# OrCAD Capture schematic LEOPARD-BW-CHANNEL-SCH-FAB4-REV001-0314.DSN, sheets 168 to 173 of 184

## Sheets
168 120_POWER/RESET BUTTON: size Custom; title: POWER/RESET BUTTON
169 036_CPU1 - GROUND (1/2): size A3; title: CPU1 - GROUND (1/2)
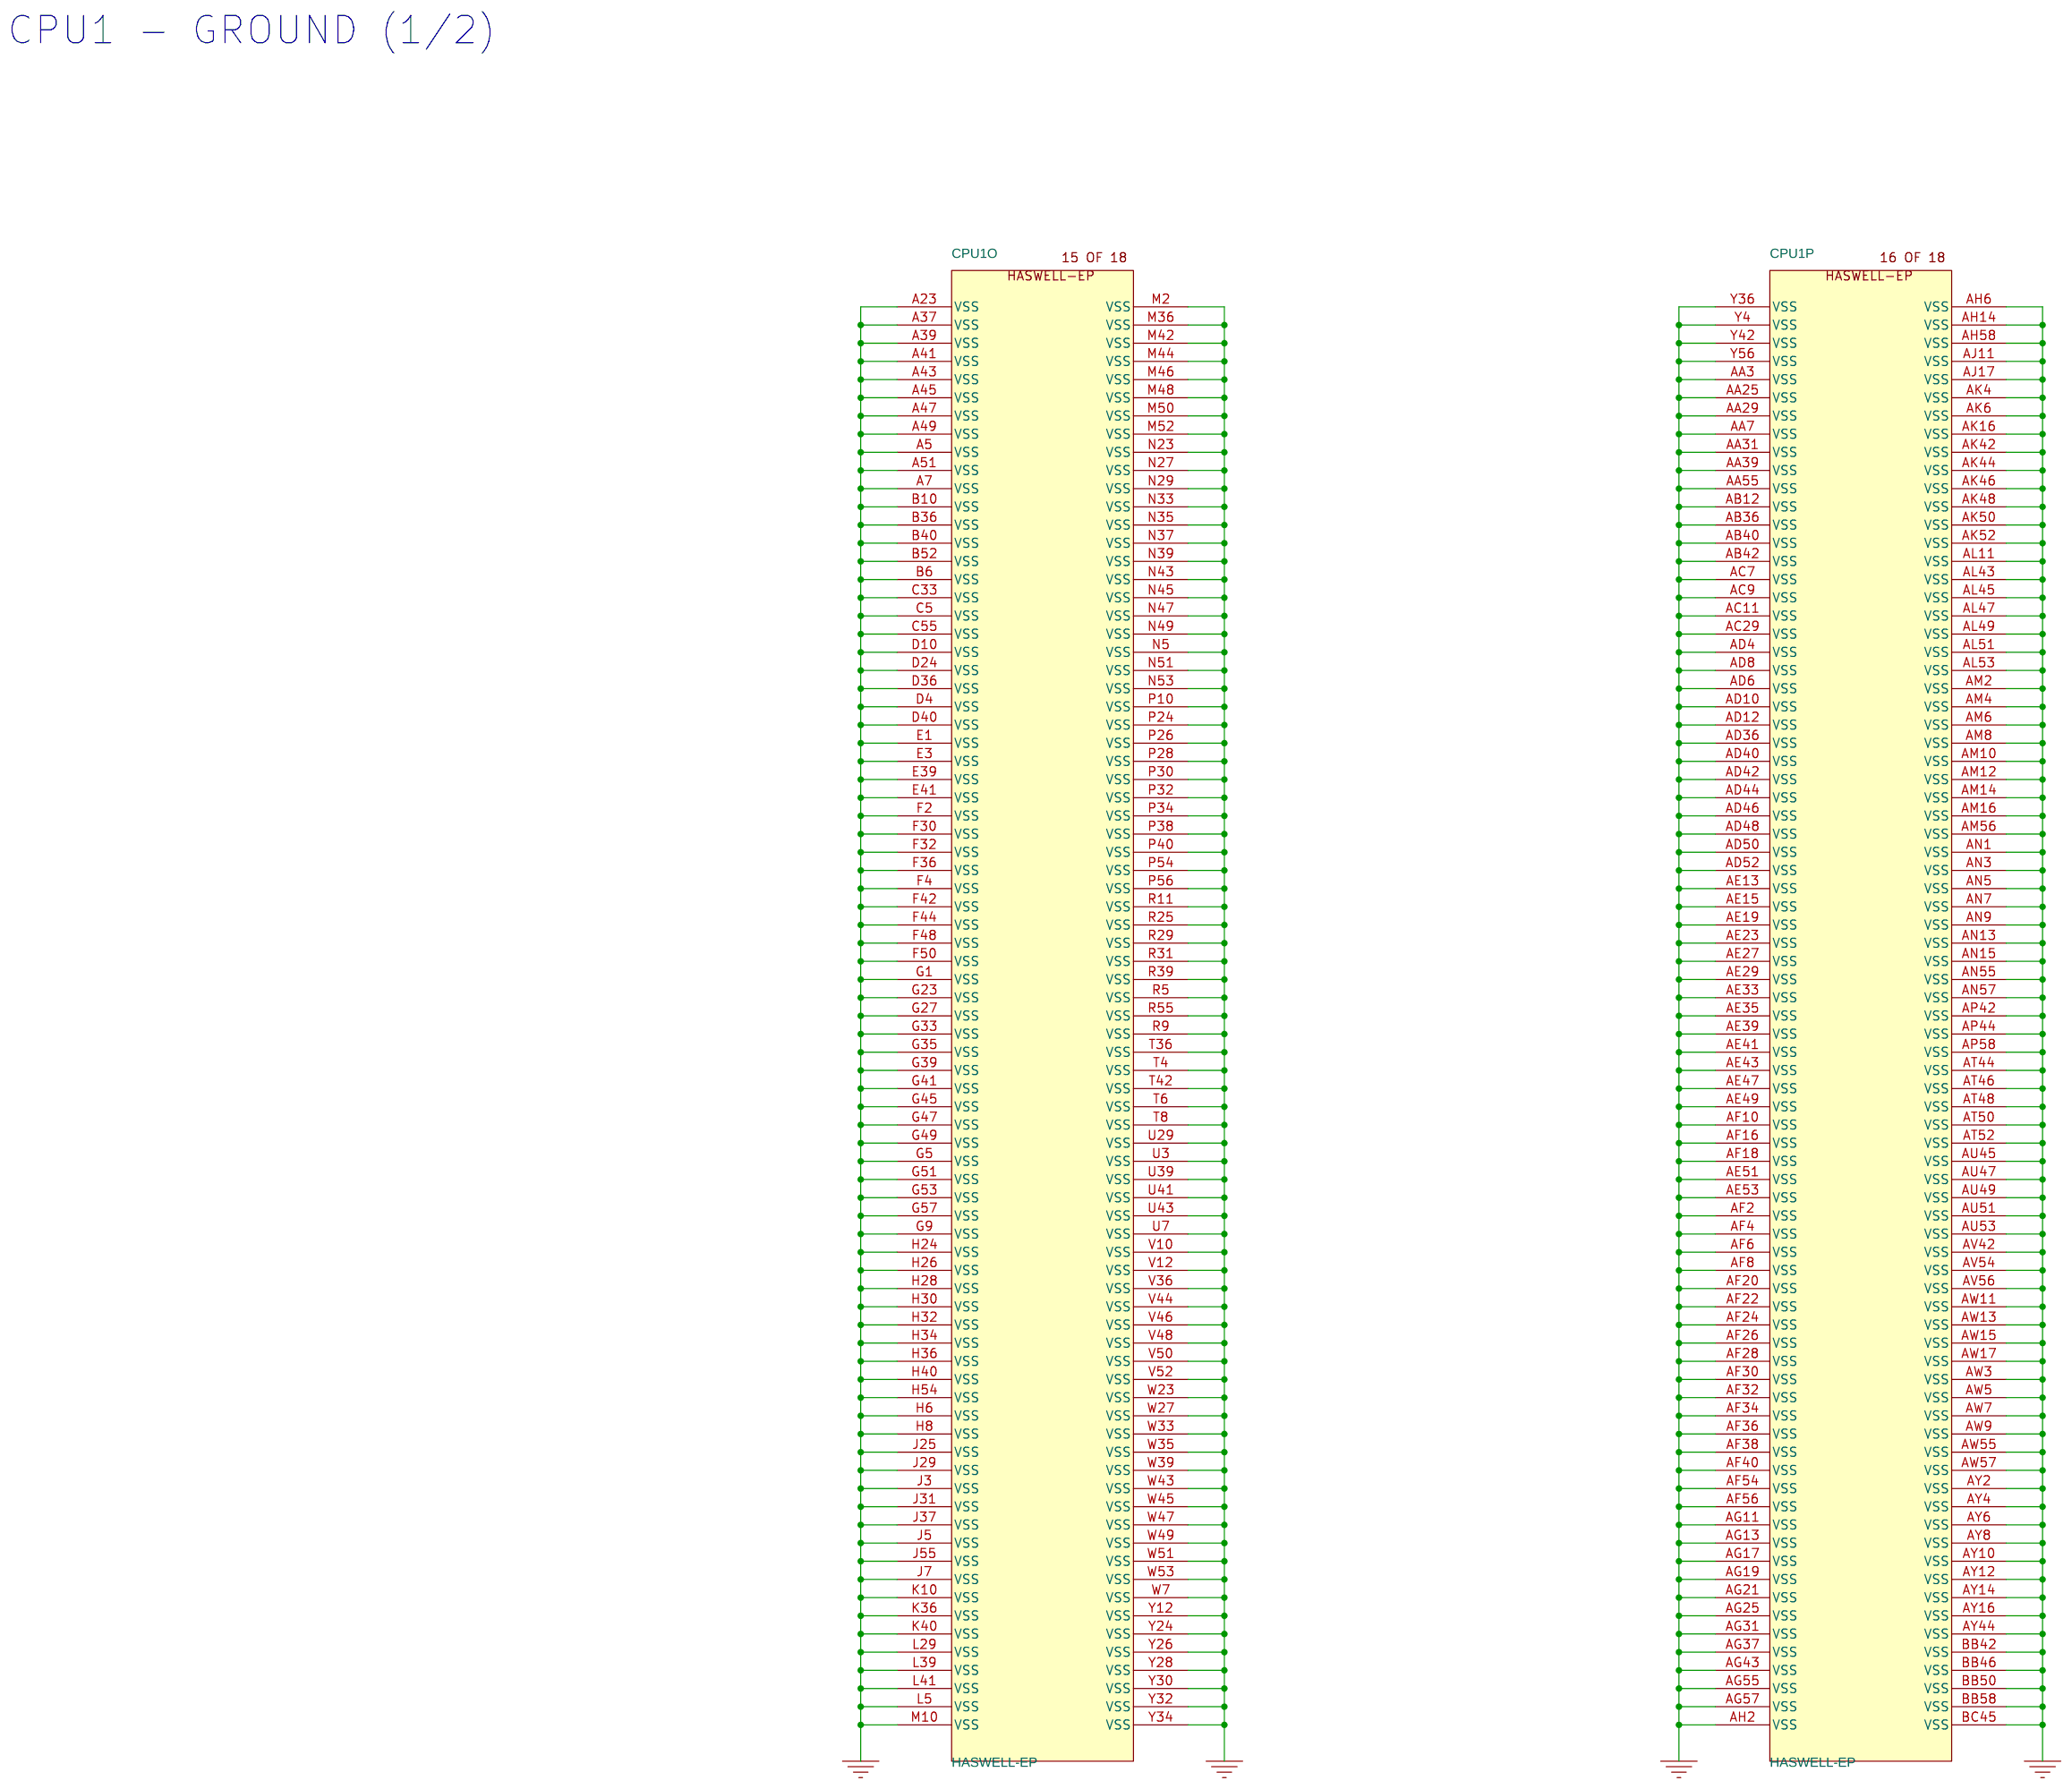
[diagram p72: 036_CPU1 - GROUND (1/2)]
170 037_CPU1 - GROUND (2/2): size A3; title: CPU1 - GROUND (2/2)
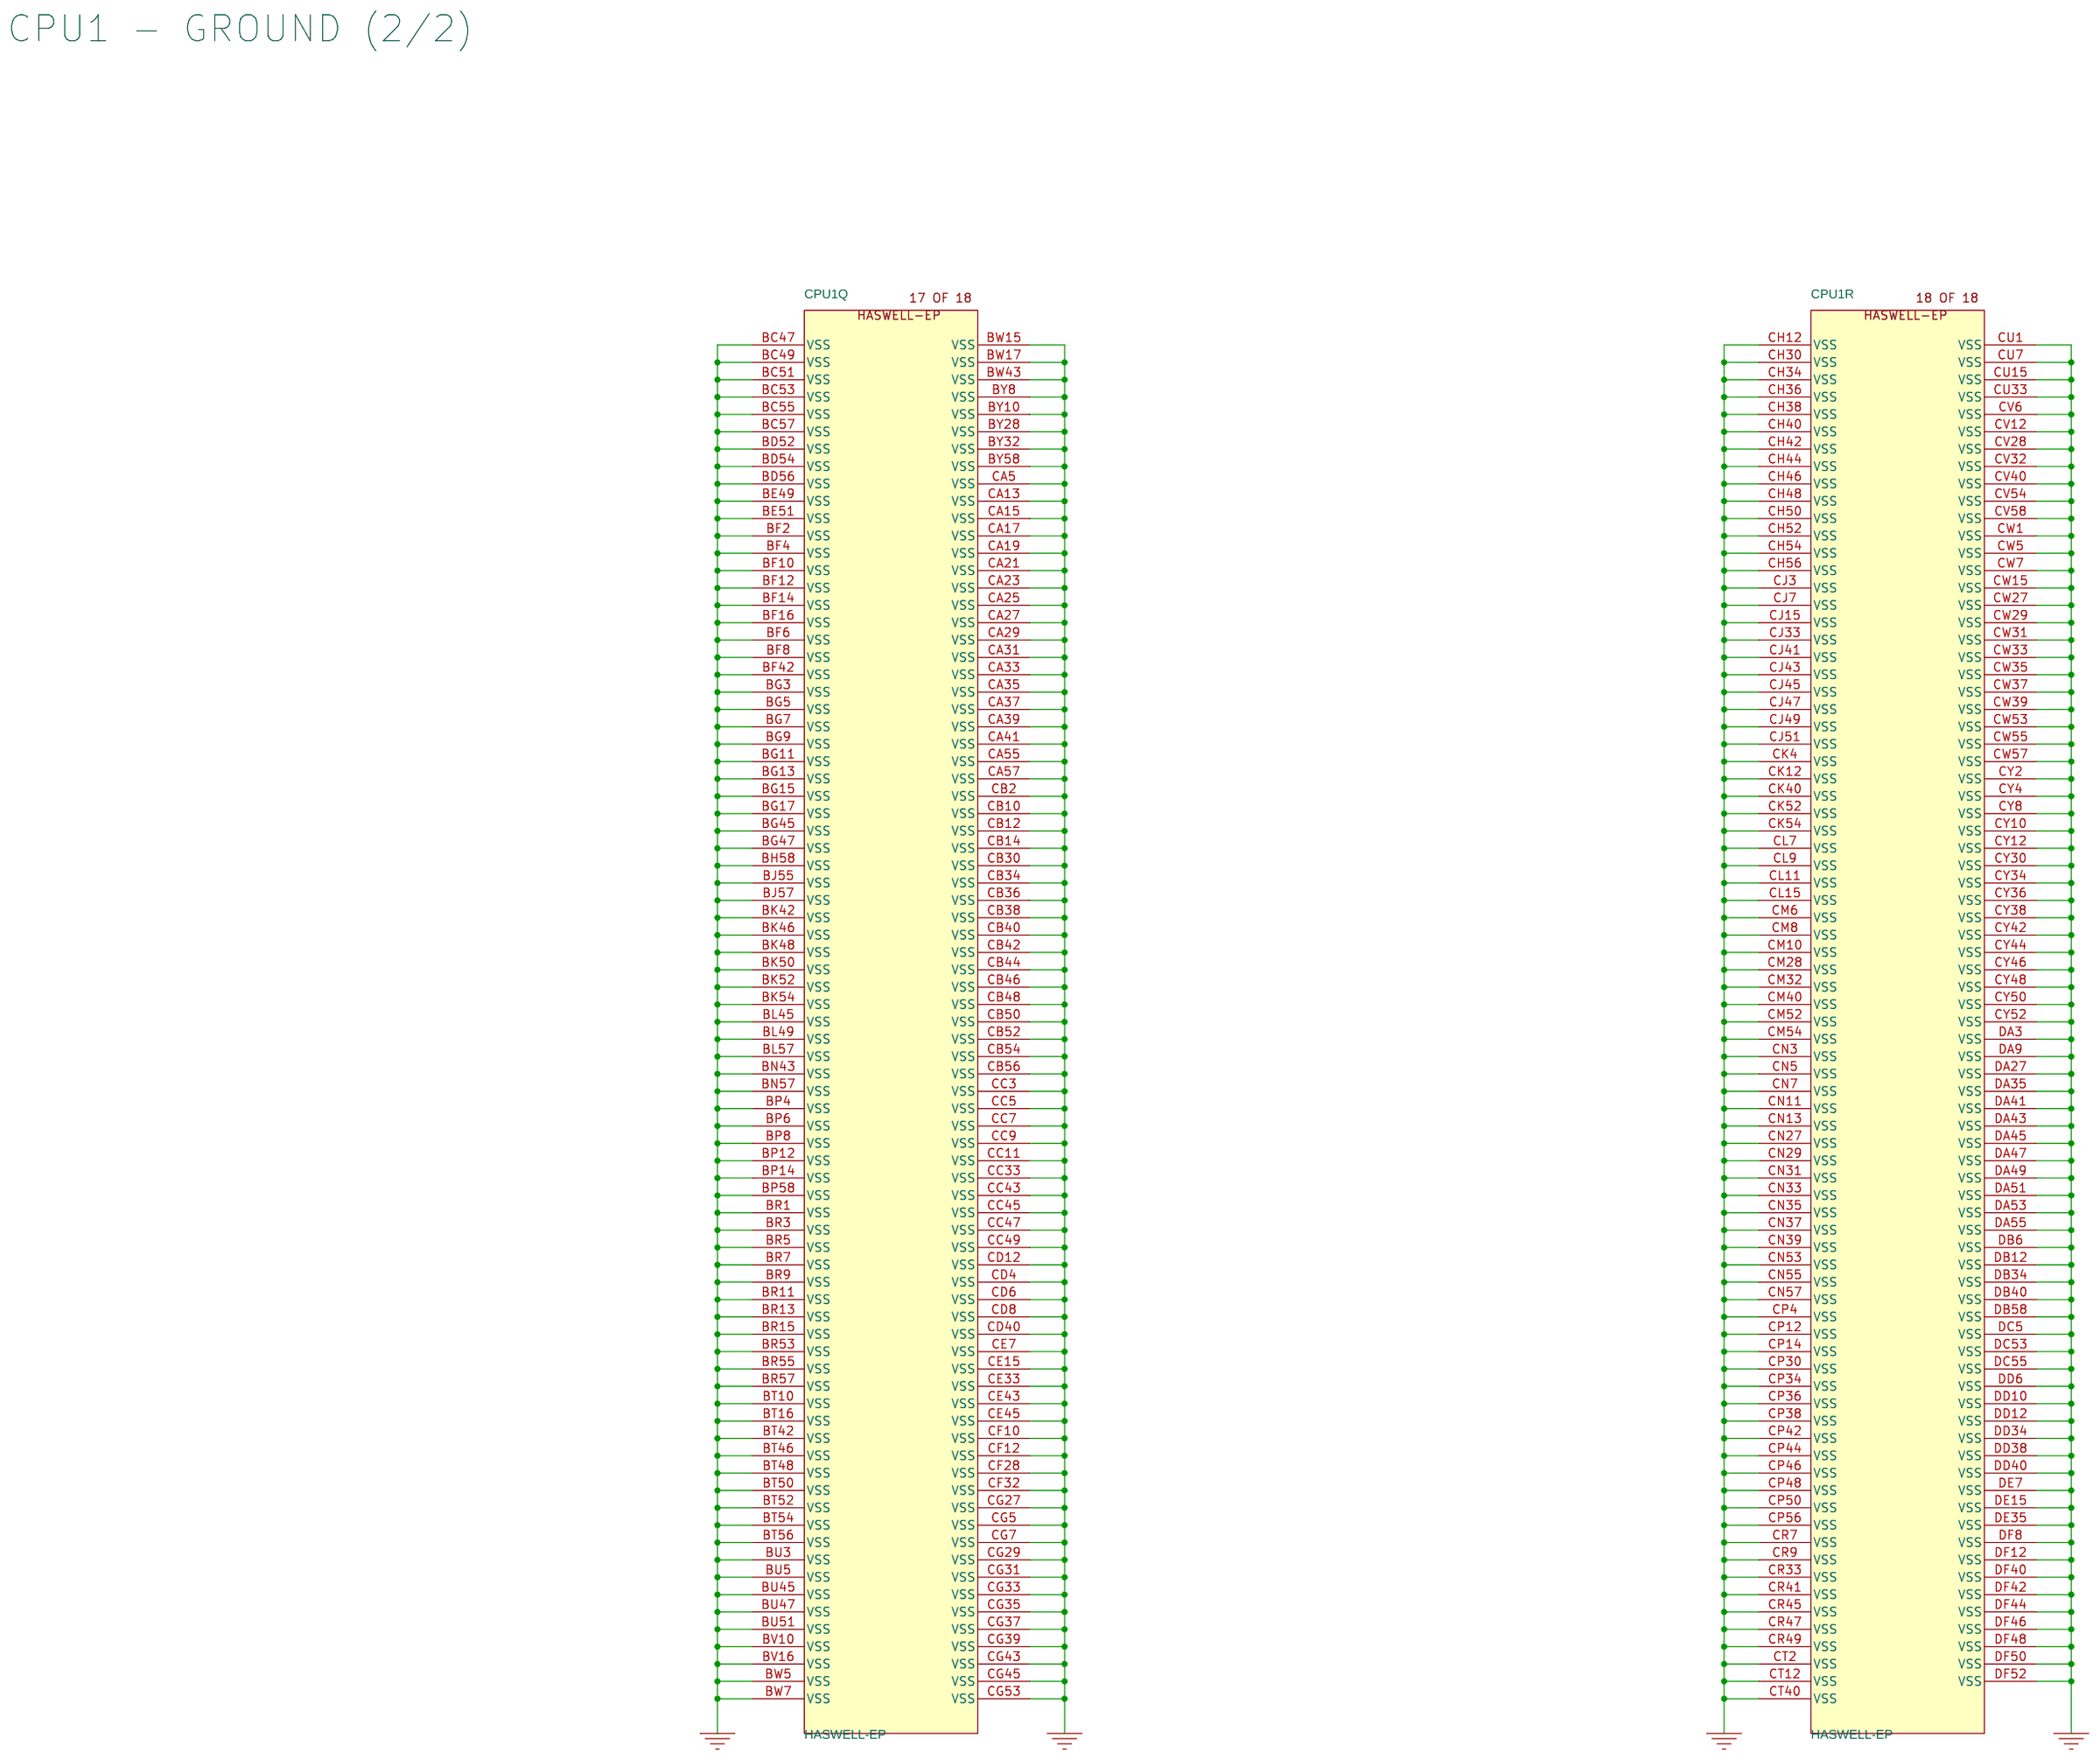
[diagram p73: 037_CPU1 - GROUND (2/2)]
171 051_CPU2 - GROUND (2/2): size A3; title: CPU2 - GROUND (2/2)
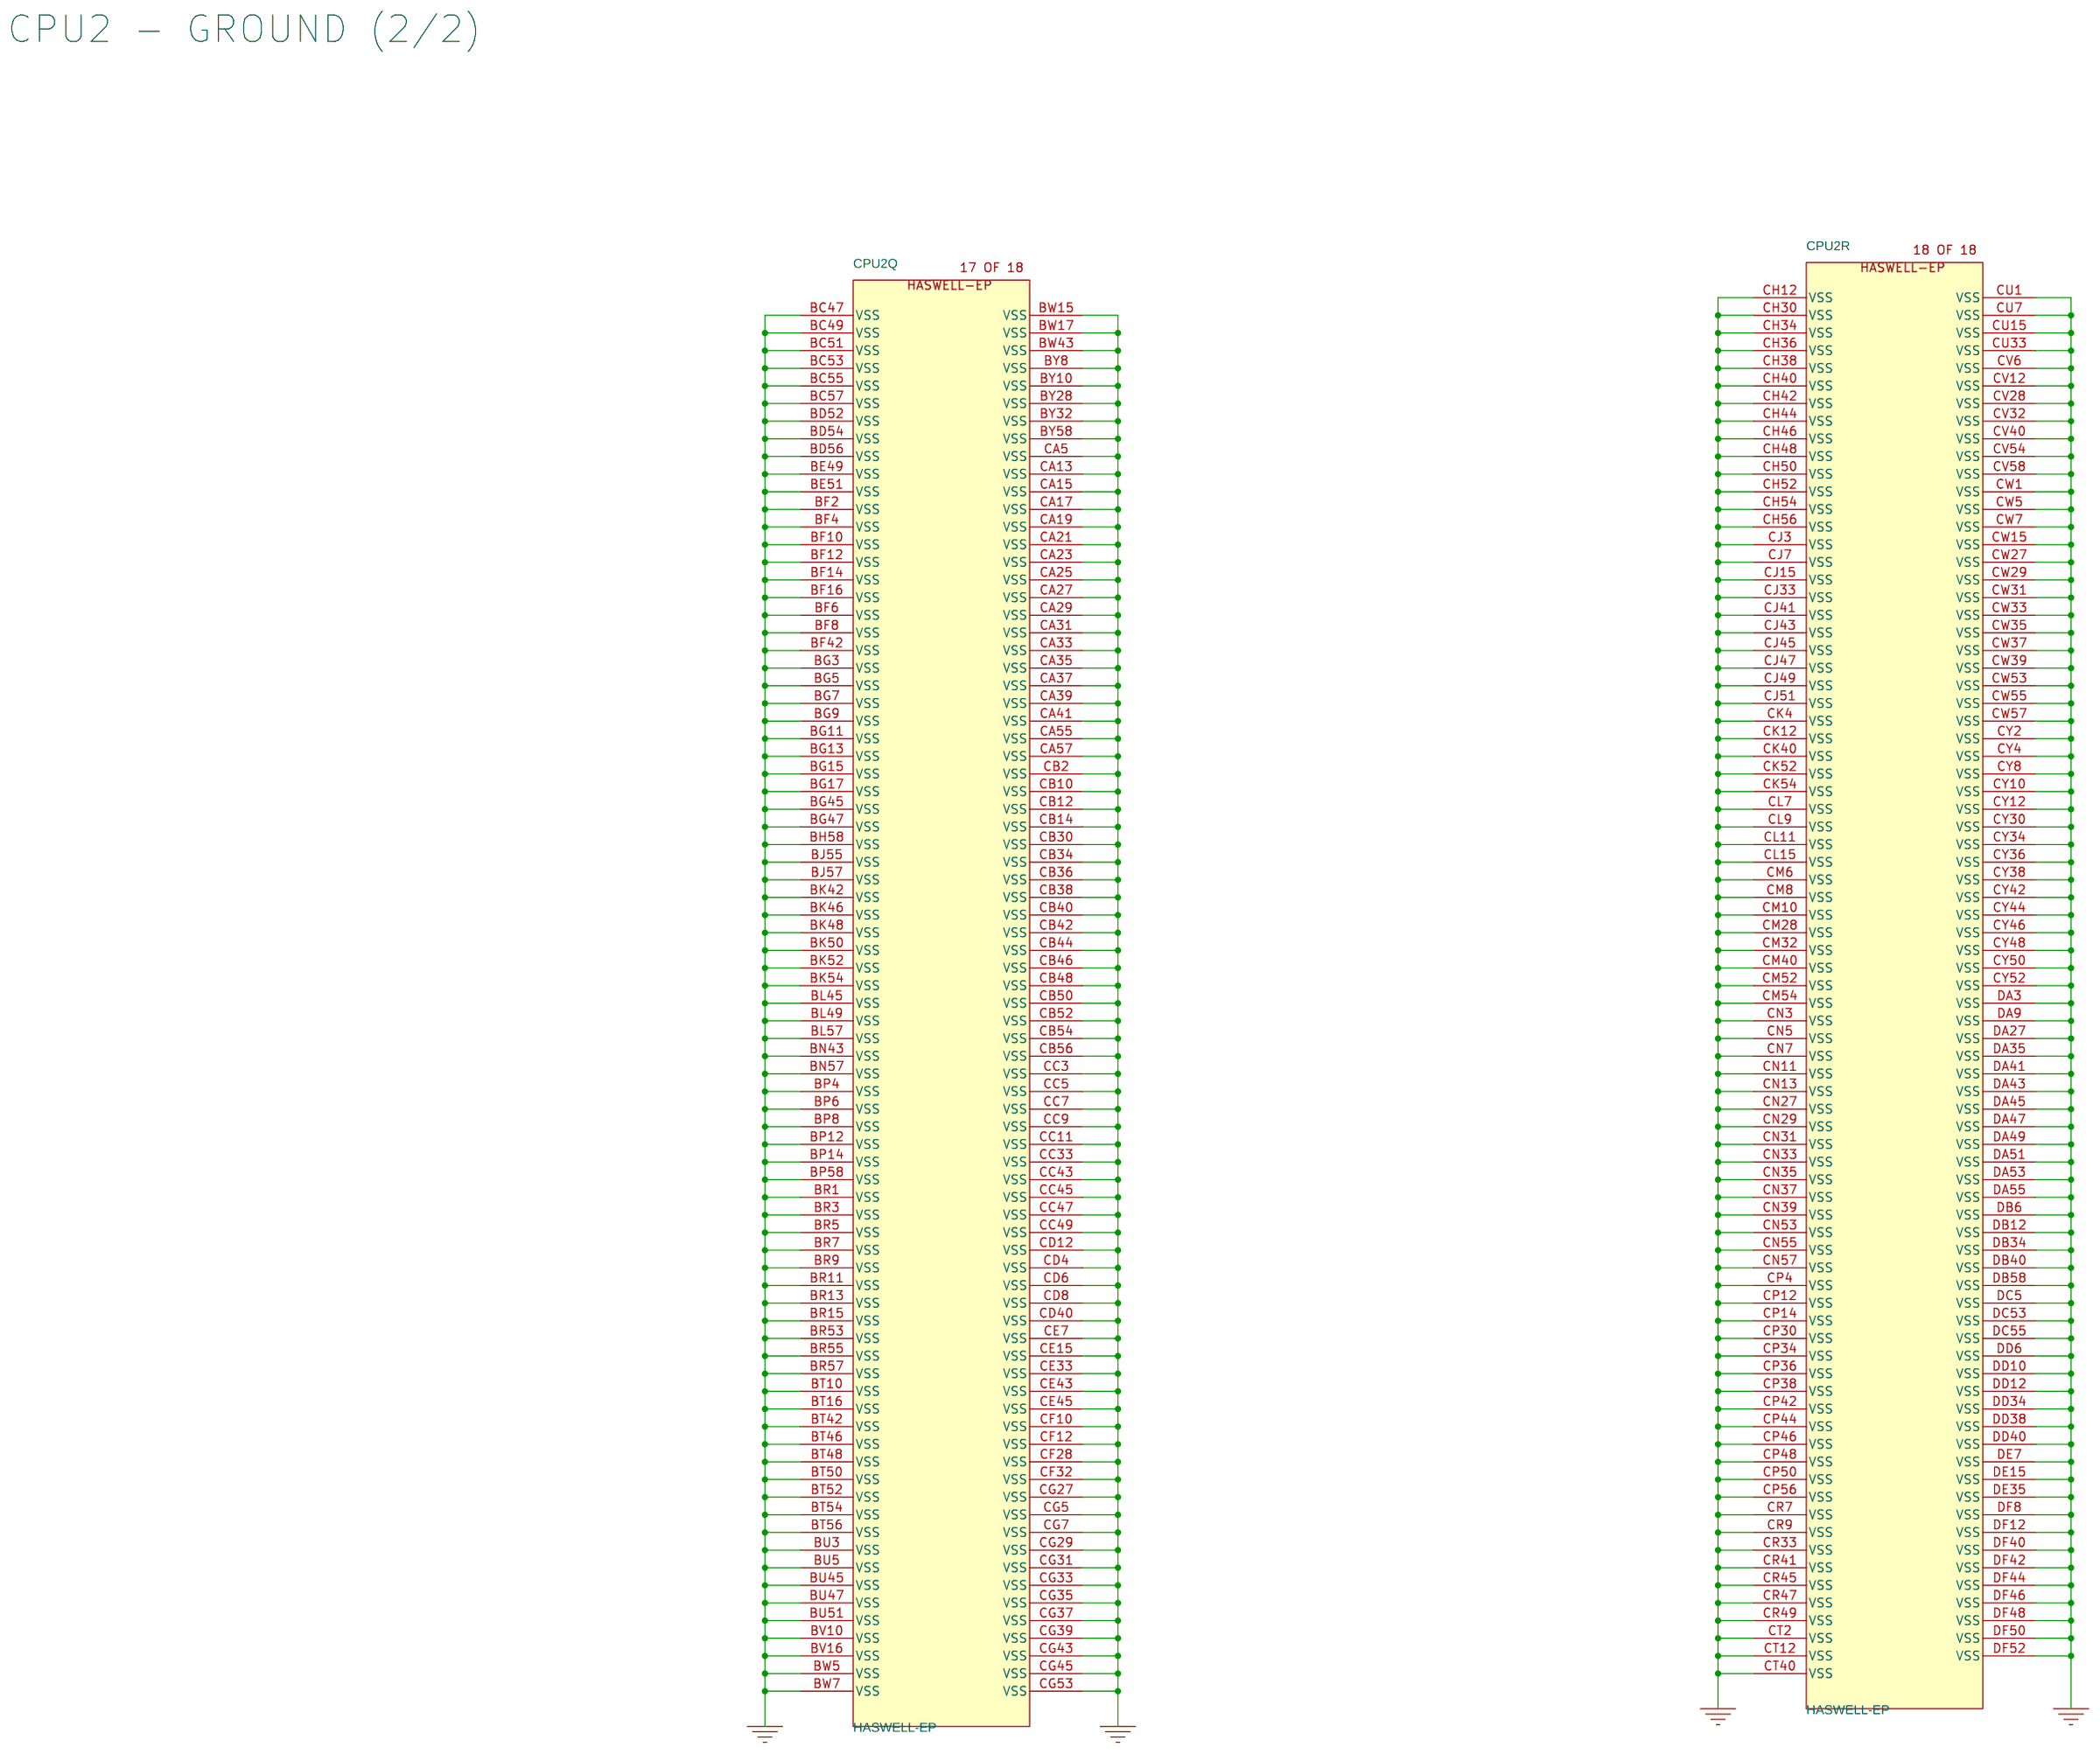
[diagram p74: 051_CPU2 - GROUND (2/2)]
172 050_CPU2 - GROUND (1/2): size A3; title: CPU2 - GROUND
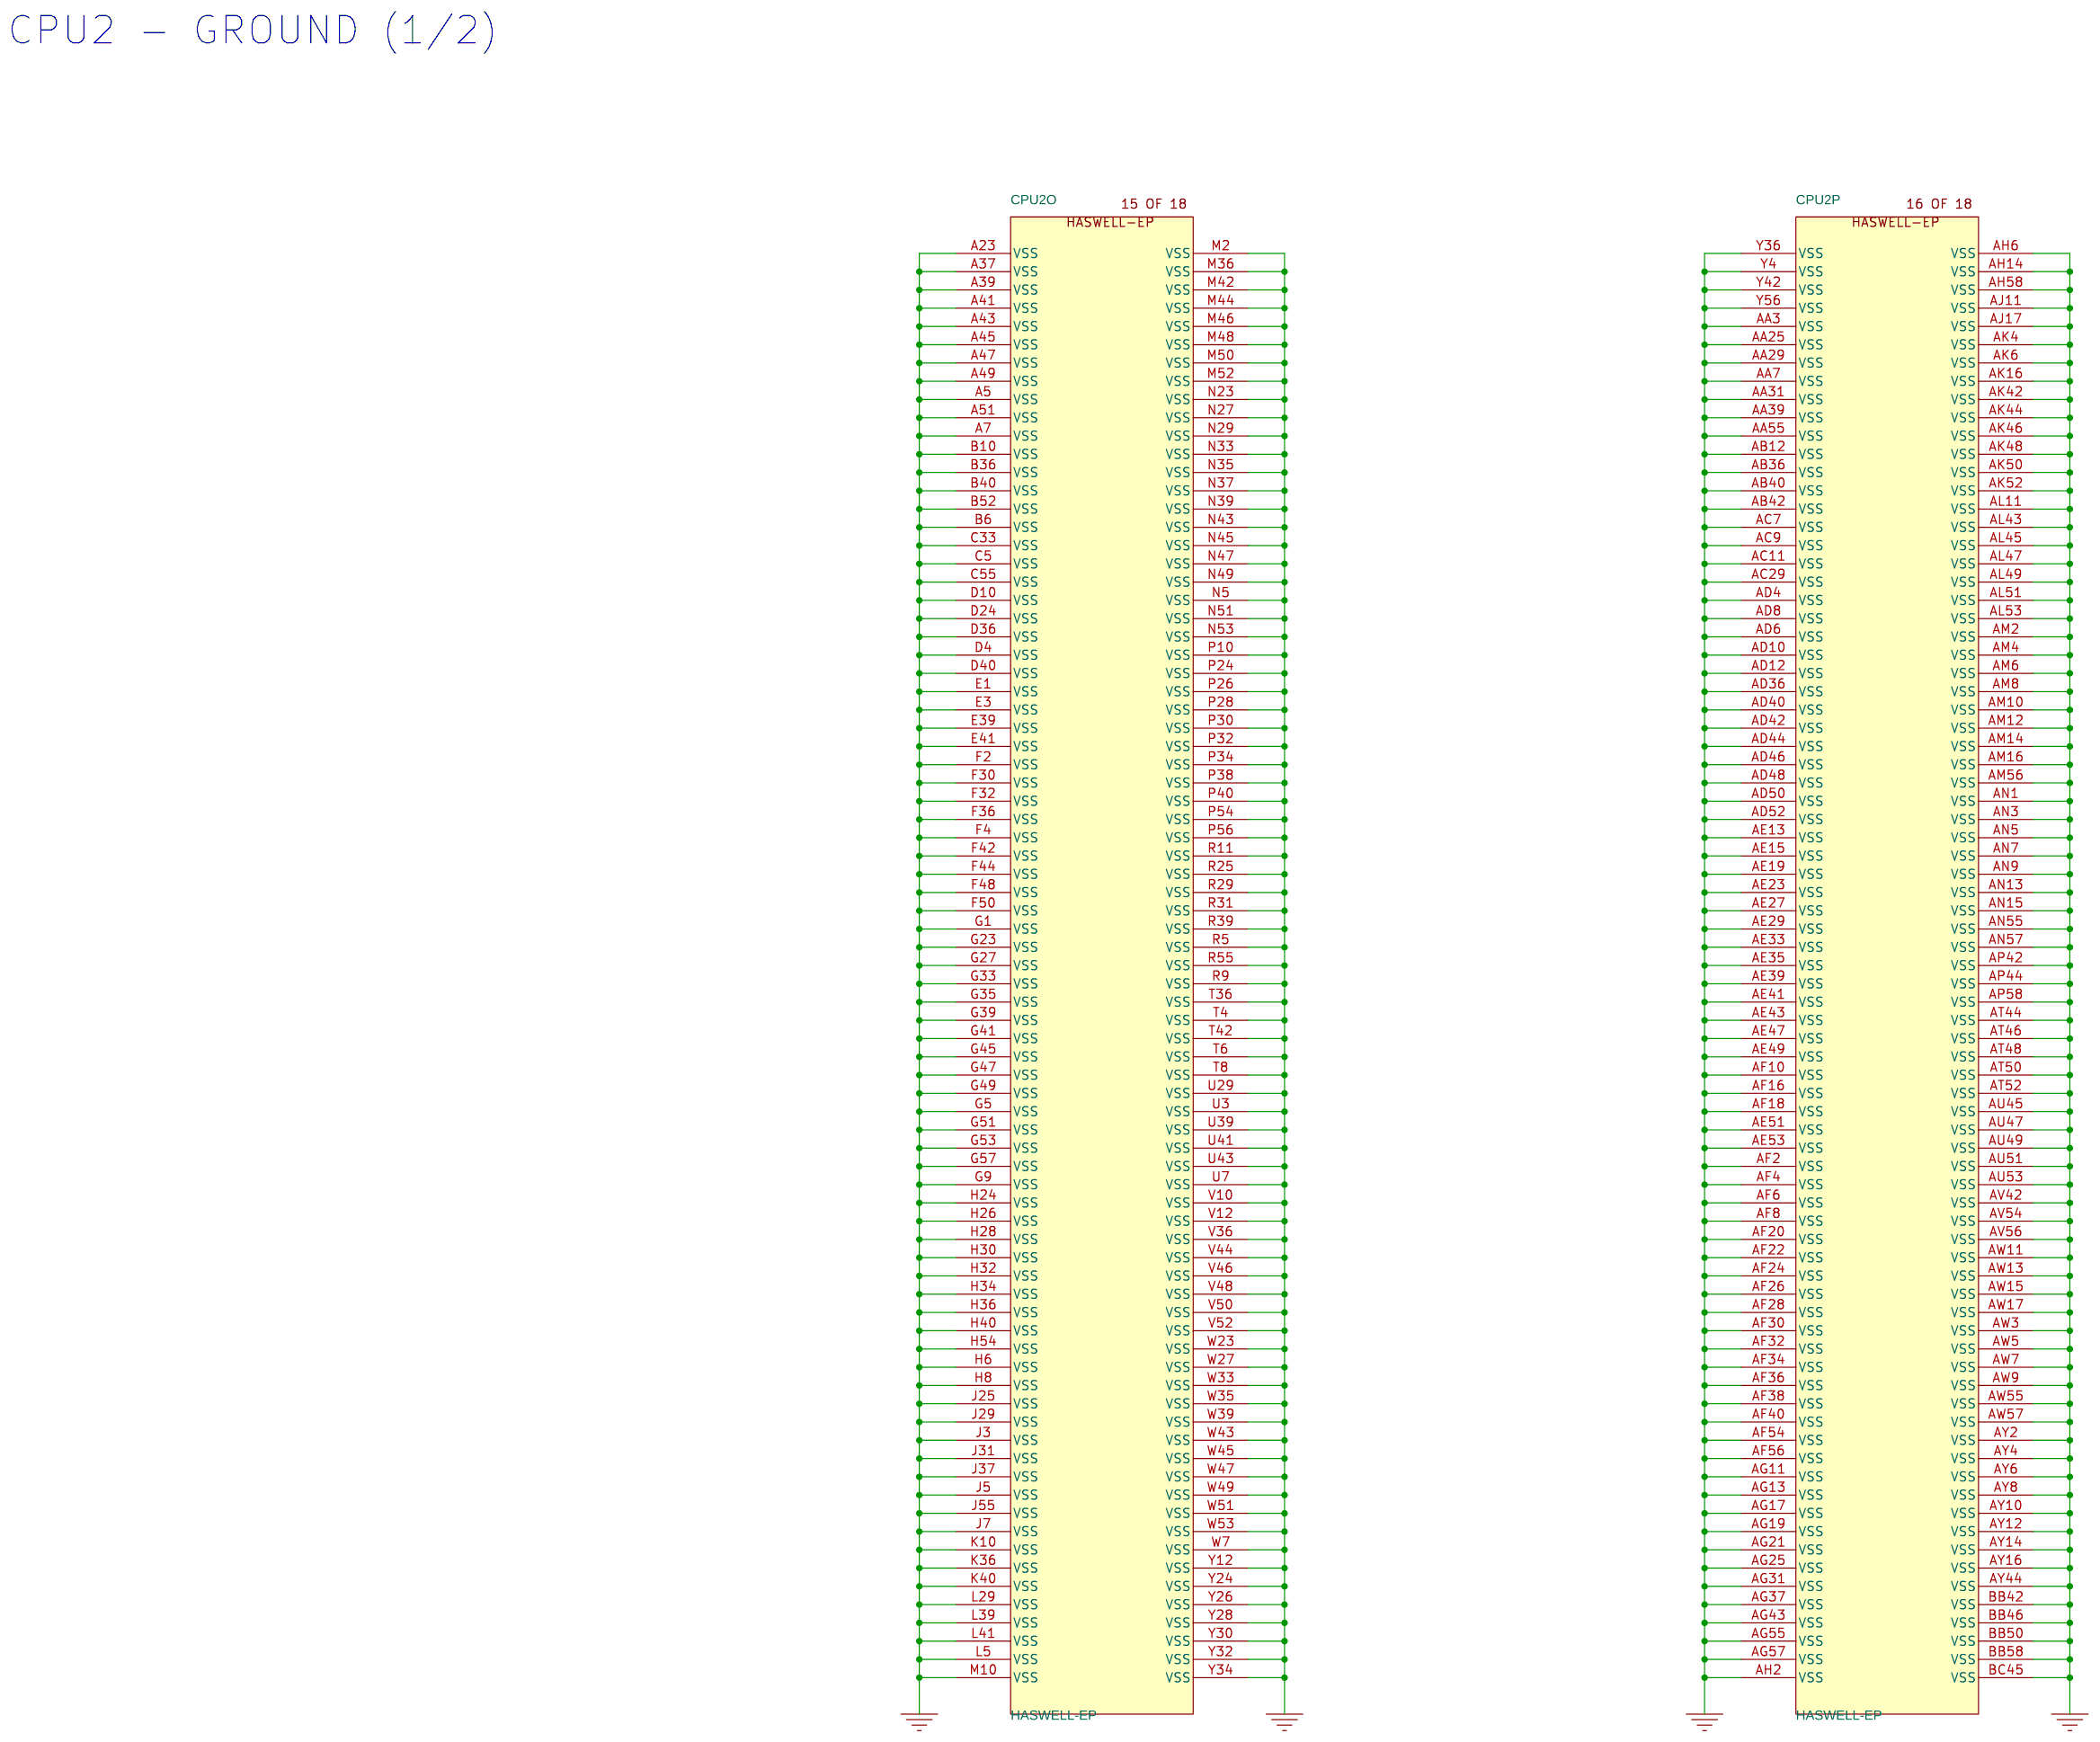
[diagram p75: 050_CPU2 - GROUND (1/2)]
173 091_WBG - DECOUPLING 1/2: size A3; title: WBG - DECOUPLING 1/2

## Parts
sheet 035_CPU1 - VCCIN & VDDQ
CPU1  HASWELL-EP  [SKT-LGA2011M6151-1H298]  (sections A,B,C,D,E,F,G,H,I,J,K,L,M,N,O,P,Q,R)
sheet 041_CPU2 - DDR4 (CHANNEL F)
CPU2  HASWELL-EP  [SKT-LGA2011M6151-1H298]  (sections A,B,C,D,E,F,G,H,I,J,K,L,M,N,O,P,Q,R)
sheet 091_WBG - DECOUPLING 1/2
C222  SC1U10V2KX-4-GP  [C402H22]
C223  SC1U10V2KX-4-GP  [C402H22]
C224  SC22U6D3V5MX-5-GP  [C805H56]
C225  SC1U10V2KX-4-GP  [C402H22]
C226  SC1U10V2KX-4-GP  [C402H22]
C227  SCD1U16V2KX-3GP  [C402H22]
C228  SCD1U16V2KX-3GP  [C402H22]
C229  SC1U10V2KX-4-GP  [C402H22]
C230  SC1U10V2KX-4-GP  [C402H22]
C231  SC1U10V2KX-4-GP  [C402H22]
C232  SC10U6D3V5KX-4GP  [C805H58]
C233  SC1U10V2KX-4-GP  [C402H22]
C234  SCD1U16V2KX-3GP  [C402H22]
C235  SCD1U16V2KX-3GP  [C402H22]
C236  SCD1U16V2KX-3GP  [C402H22]
C237  SC1U10V2KX-4-GP  [C402H22]
C238  SCD1U16V2KX-3GP  [C402H22]
C239  SC1U10V2KX-4-GP  [C402H22]
C240  SCD1U16V2KX-3GP  [C402H22]
C241  SC1U10V2KX-4-GP  [C402H22]
C242  SC1U10V2KX-4-GP  [C402H22]
C243  SC1U10V2KX-4-GP  [C402H22]
C244  SC1U10V2KX-4-GP  [C402H22]
C245  SC10U6D3V5KX-4GP  [C805H58]
C246  SCD1U16V2KX-3GP  [C402H22]
C247  SCD1U16V2KX-3GP  [C402H22]
C248  SCD01U25V2KX-3GP  [C402H22]
C249  SCD01U25V2KX-3GP  [C402H22]
C250  SCD01U25V2KX-3GP  [C402H22]
C251  SCD1U16V2KX-3GP  [C402H22]
C252  SC1U10V2KX-4-GP  [C402H22]
C253  SCD1U16V2KX-3GP  [C402H22]
C254  SC4D7U16V5KX-1-GP  [C805H56]
C255  SCD1U16V2KX-3GP  [C402H22]
C256  SCD1U16V2KX-3GP  [C402H22]
C277  SCD1U16V2KX-3GP  [C402H22]
C278  SC1U10V2KX-4-GP  [C402H22]
C279  SC10U6D3V5KX-4GP  [C805H58]
R179  5D11R2F-GP  [R402H16]
sheet 120_POWER/RESET BUTTON
C41  SCD1U16V2KX-3GP  [C402H22]
C81  SCD1U16V2KX-3GP  [C402H22]
C96  SCD1U16V2KX-3GP  [C402H22]
C315  SCD1U16V2KX-3GP  [C402H22]
C370  SC1U10V2KX-4-GP  [C402H22]
C993  SCD1U16V2KX-3GP  [C402H22]
C1002  SCD1U16V2KX-3GP  [C402H22]
C1003  SCD1U16V2KX-3GP  [C402H22]
PWRON1  SW-TACT-4P-185-GP  [DTS-65K-S-V]
Q85  2N7002-7F-GP  [SOT23DGS2D4H44]
R187  0R2J-2-GP  [R402H16]
R190  10KR2F-2-GP  [R402H16]
R216  4K7R2F-GP  [R402H16]
R219  10KR2F-2-GP  [R402H16]
R247  10KR2F-2-GP  [R402H16]
R248  10KR2F-2-GP  [R402H16]
R265  0R2J-2-GP  [R402H16]
R368  0R2J-2-GP  [R402H16]
R369  0R2J-2-GP  [R402H16]
R762  10KR2F-2-GP  [R402H16]
R1577  22KR2F-GP  [R402H16]
R1578  10KR2F-2-GP  [R402H16]
R1579  4K7R2F-GP  [R402H16]
R1580  33R2F-3-GP  [R402H16]
R1581  33R2F-3-GP  [R402H16]
R1583  0R2J-2-GP  [R402H16]
R1584  0R2J-2-GP  [R402H16]
R1586  22KR2F-GP  [R402H16]
R1587  10KR2F-2-GP  [R402H16]
R1588  4K7R2F-GP  [R402H16]
R1589  33R2F-3-GP  [R402H16]
R1592  33R2F-3-GP  [R402H16]
R1594  0R2J-2-GP  [R402H16]
R1596  0R2J-2-GP  [R402H16]
R1605  0R2J-2-GP  [R402H16]
R1635  0R2J-2-GP  [R402H16]
R1894  1KR2J-1-GP  [R402H16]
R1895  10KR2J-3-GP  [R402H16]
R1896  0R2J-2-GP  [R402H16]
R1897  0R2J-2-GP  [R402H16]
R1906  0R2J-2-GP  [R402H16]
R1907  0R2J-2-GP  [R402H16]
R1908  0R2J-2-GP  [R402H16]
R1912  0R2J-2-GP  [R402H16]
R1913  10KR2J-3-GP  [R402H16]
R1914  0R2J-2-GP  [R402H16]
R2054  4K7R2F-GP  [R402H16]
RESET1  SW-TACT-4P-184-GP  [DTS-65K-S-V]
U102  74LVC2G74GD-GP  [XSON8H20]
U103  74AHC1G32DBVR-GP  [SOT-23-5H58]
U170  TSLVC07APW-GP  [TSOIC14H44]  (sections A,B,C,D,E,F)
U171  SNLVC1G126DCKR-GP  [SC70-5H44]
U172  SNLVC1G08DCKRG4-GP  [SC70-5H44]
U173  SNLVC1G126DCKR-GP  [SC70-5H44]
U174  SNLVC1G08DCKRG4-GP  [SC70-5H44]
U175  TSLVC14APW-2-GP  [TSOIC14H44]  (sections A,B,C,D,E,F)

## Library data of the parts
CPU1 CPU2 = HASWELL-EP: SKT CPU LGA 2011P AZIF0001-P004C SMD; GREENDFACTOR: R2_C;; POP?: 62.10079.311; Package Type: SOCKET-G2; Part Number: 62.10079.261; SPEC: http://wpqssvr.wistron.com.tw:7001/wpqs/servlet/COM.qpart.Attachment?PartNumber=62.10079.261
C222 C223 C225 C226 C229-C231 C233 C237 C239 C241-C244 C252 C278 C370 = SC1U10V2KX-4-GP: CHIP CAP C 1U 10V K 0402 X6S; GREENDFACTOR: R2_SA;HF_SA;; Part Number: 78.10523.8FL; Part Type: SMD-BCG6; SPEC: http://wpqssvr.wistron.com.tw:7001/wpqs/servlet/COM.qpart.Attachment?PartNumber=78.10523.8FL
C224 = SC22U6D3V5MX-5-GP: CHIP CAP C 22U 6.3V M0805 X6S; GREENDFACTOR: R2_SA;HF_SA;G_SA;; Part Number: 78.22610.81L; Part Type: SMD-BCG2; SPEC: http://wpqssvr.wistron.com.tw:7001/wpqs/servlet/COM.qpart.Attachment?PartNumber=78.22610.81L
C227 C228 C234-C236 C238 C240 C246 C247 C251 C253 C255 C256 C277 = SCD1U16V2KX-3GP: CHIP CAP C 0.1U 16V K0402 X7R; Category: CLK GEN; GREENDFACTOR: R_SA;HF_SA;G_SA;; Part Number: 78.10421.2FL; Quotation: 12_14; Type: SMD
C232 C245 C279 = SC10U6D3V5KX-4GP: CHIP CAP C 10U 6.3V K0805 X7R; GREENDFACTOR: R2_SA;HF_SA;G_SA;; Part Number: 78.10620.21L; Part Type: SMD-BCG; SPEC: http://wpqssvr.wistron.com.tw:7001/wpqs/servlet/COM.qpart.Attachment?PartNumber=78.10620.21L
C248-C250 = SCD01U25V2KX-3GP: CHIP 0.01U 25V K0402 X7R(ROHS); Category: BMC; GREENDFACTOR: R2_SA;HF_SA;G_SA;; Level: SMD; Part Number: 78.10322.2FL; Part Type: SMD-BCG; SPEC: http://wpqssvr.wistron.com.tw:7001/wpqs/servlet/COM.qpart.Attachment?PartNumber=78.10322.2FL; Status: POP
C254 = SC4D7U16V5KX-1-GP: CHIP CAP C 4.7U 16V K0805 X7R; GREENDFACTOR: R2_SA;HF_SA;G_SA;; Part Number: 78.47521.21L; Part Type: SMD-BCG2; SPEC: http://wpqssvr.wistron.com.tw:7001/wpqs/servlet/COM.qpart.Attachment?PartNumber=78.47521.21L
R179 = 5D11R2F-GP: CHIP RES 5.11 F 1/16W 0402; Category: PCH; Part Number: 64.5R115.6DL; Part Type: SMD-RG2
C41 C315 C1002 C1003 = SCD1U16V2KX-3GP: CHIP CAP C 0.1U 16V K0402 X7R; CATEGORIES: CAP_1.xV; GREENDFACTOR: R2_SA;HF_SA;G_SA;; MAIN_SOURCE: M; Part Number: 78.10421.2FL; Part Type: SMD-BCG; SPEC: http://wpqssvr.wistron.com.tw:7001/wpqs/servlet/COM.qpart.Attachment?PartNumber=78.10421.2FL
C81 C96 = SCD1U16V2KX-3GP: CHIP CAP C 0.1U 16V K0402 X7R; CATEGORIES: CAP_1.xV; GREENDFACTOR: R2_SA;HF_SA;G_SA;; MAIN_SOURCE: M; POP?: NOPOP; Part Number: 78.10421.2FL; Part Type: SMD-BCG; SPEC: http://wpqssvr.wistron.com.tw:7001/wpqs/servlet/COM.qpart.Attachment?PartNumber=78.10421.2FL
C993 = SCD1U16V2KX-3GP: CHIP CAP C 0.1U 16V K0402 X7R; Belong: POP; CATEGORIES: CAP_1.xV; Category: LED_WOL; GREENDFACTOR: R2_SA;HF_SA;G_SA;; MAIN_SOURCE: M; Part Number: 78.10421.2FL; Part Type: SMD-BCG; SPEC: http://wpqssvr.wistron.com.tw:7001/wpqs/servlet/COM.qpart.Attachment?PartNumber=78.10421.2FL
PWRON1 = SW-TACT-4P-185-GP: SW TACT 4P DTS-65R-Q; GREENDFACTOR: R2_SA;; Part Number: 22.40069.J01; Part Type: DISCRET-GC1; SPEC: http://wpqssvr.wistron.com.tw:7001/wpqs/servlet/COM.qpart.Attachment?PartNumber=22.40069.J01
Q85 = 2N7002-7F-GP: FET MOS 2N7002-7-F NC SOT-23; GREENDFACTOR: R2_SA;HF_SA;G_SA;; POP?: NOPOP; Part Number: 84.27002.N31; Part Type: DISCRET-G; SPEC: http://wpqssvr.wistron.com.tw:7001/wpqs/servlet/COM.qpart.Attachment?PartNumber=84.27002.N31
R187 R265 = 0R2J-2-GP: CHIP RES 0 J 1/16W 0402; Category: Logic; DESCRIPTIO: CHIP RES 0 J 1/16W 0402; GREENDFACTOR: R2_SA;HF_SA;G_SA;; POP?: NOPOP; Package Type: SMD-RG; Part Number: 63.R0034.1DL; Part Type: SMD-RG; SPEC: http://wpqssvr.wistron.com.tw:7001/wpqs/servlet/COM.qpart.Attachment?PartNumber=63.R0034.1DL; VENDORPARTNUMBER: RM04JTN0/RTT02000JTH/RR0510X-000-XN/RC0402JR-070RL/WR04X000 PTL
R190 = 10KR2F-2-GP: CHIP RES 10K F 1/16W 0402; Category: PCH; DESCRIPTIO: CHIP RES 10K F 1/16W 0402; GREENDFACTOR: R2_SA;HF_SA;G_SA;; Package Type: SMD-RG; Part Number: 64.10025.6DL; Part Type: SMD-RG; SPEC: http://wpqssvr.wistron.com.tw:7001/wpqs/servlet/COM.qpart.Attachment?PartNumber=64.10025.6DL; VENDORPARTNUMBER: RM04FTN1002 / RTT021002FTH / RR0510S-103-FN / RC0402FR-0710KL/WR04X1002FTL
R216 R2054 = 4K7R2F-GP: CHIP RES 4.7K F 1/16W 0402; Category: BMC; DESCRIPTIO: CHIP RES 4.7K F 1/16W 0402; GREENDFACTOR: R2_SA;HF_SA;G_SA;; POP?: NOPOP; Package Type: RCL_GP; Part Number: 64.47015.6DL; Part Type: RCL_GP; SPEC: http://wpqssvr.wistron.com.tw:7001/wpqs/servlet/COM.qpart.Attachment?PartNumber=64.47015.6DL; VENDORPARTNUMBER: RM04FTN4701/RTT024701FTH/RR0510S-472-FN/RC0402FR-074K7L/WR04X4701FTL
R219 R247 R248 R762 R1578 R1587 = 10KR2F-2-GP: CHIP RES 10K F 1/16W 0402; Category: internal conn; DESCRIPTIO: CHIP RES 10K F 1/16W 0402; GREENDFACTOR: R2_SA;HF_SA;G_SA;; Package Type: SMD-RG; Part Number: 64.10025.6DL; Part Type: SMD-RG; SPEC: http://wpqssvr.wistron.com.tw:7001/wpqs/servlet/COM.qpart.Attachment?PartNumber=64.10025.6DL; VENDORPARTNUMBER: RM04FTN1002 / RTT021002FTH / RR0510S-103-FN / RC0402FR-0710KL/WR04X1002FTL
R368 R369 R1583 R1584 R1594 R1596 R1605 = 0R2J-2-GP: CHIP RES 0 J 1/16W 0402; Category: Logic; DESCRIPTIO: CHIP RES 0 J 1/16W 0402; GREENDFACTOR: R2_SA;HF_SA;G_SA;; Package Type: SMD-RG; Part Number: 63.R0034.1DL; Part Type: SMD-RG; SPEC: http://wpqssvr.wistron.com.tw:7001/wpqs/servlet/COM.qpart.Attachment?PartNumber=63.R0034.1DL; VENDORPARTNUMBER: RM04JTN0/RTT02000JTH/RR0510X-000-XN/RC0402JR-070RL/WR04X000 PTL
R1577 R1586 = 22KR2F-GP: CHIP RES 22K F 1/16W 0402; Category: internal conn; DESCRIPTIO: CHIP RES 22K F 1/16W 0402; GREENDFACTOR: R2_SA;HF_SA;G_SA;; Package Type: RCL_GP; Part Number: 64.22025.6DL; Part Type: RCL_GP; SPEC: http://wpqssvr.wistron.com.tw:7001/wpqs/servlet/COM.qpart.Attachment?PartNumber=64.22025.6DL; VENDORPARTNUMBER: RM04FTN2202 / RTT022202FTH / RR0510S-2202-FN / RC0402FR-0722KL/WR04X2202FTL
R1579 = 4K7R2F-GP: CHIP RES 4.7K F 1/16W 0402; Category: internal conn; DESCRIPTIO: CHIP RES 4.7K F 1/16W 0402; GREENDFACTOR: R2_SA;HF_SA;G_SA;; POP?: NOPOP; Package Type: RCL_GP; Part Number: 64.47015.6DL; Part Type: RCL_GP; SPEC: http://wpqssvr.wistron.com.tw:7001/wpqs/servlet/COM.qpart.Attachment?PartNumber=64.47015.6DL; VENDORPARTNUMBER: RM04FTN4701/RTT024701FTH/RR0510S-472-FN/RC0402FR-074K7L/WR04X4701FTL
R1580 R1581 R1589 R1592 = 33R2F-3-GP: CHIP RES 33 F 1/16W 0402(ROHS); Category: internal conn; DESCRIPTIO: CHIP RES 33 F 1/16W 0402(ROHS); GREENDFACTOR: R2_SA;HF_SA;G_SA;; Package Type: SMD-RG; Part Number: 64.33R05.6DL; Part Type: SMD-RG; SPEC: http://wpqssvr.wistron.com.tw:7001/wpqs/servlet/COM.qpart.Attachment?PartNumber=64.33R05.6DL; VENDORPARTNUMBER: RM04FTN33R0/RTT0233R0FTH/RR0510S-330-FN/RC0402FR-0733RL/WR04X33R0FTL
R1588 = 4K7R2F-GP: CHIP RES 4.7K F 1/16W 0402; Category: internal conn; DESCRIPTIO: CHIP RES 4.7K F 1/16W 0402; GREENDFACTOR: R2_SA;HF_SA;G_SA;; Package Type: RCL_GP; Part Number: 64.47015.6DL; Part Type: RCL_GP; SPEC: http://wpqssvr.wistron.com.tw:7001/wpqs/servlet/COM.qpart.Attachment?PartNumber=64.47015.6DL; VENDORPARTNUMBER: RM04FTN4701/RTT024701FTH/RR0510S-472-FN/RC0402FR-074K7L/WR04X4701FTL
R1635 = 0R2J-2-GP: CHIP RES 0 J 1/16W 0402; Belong: POP; Category: LED_WOL; GREENDFACTOR: R_SA;HF_SA;G_SA;; MP_POP?: N/A; Module: Internal Connector; Part Number: 63.R0034.1DL; Part Type: SMD-RG; SPEC: http://wpqssvr.wistron.com.tw:7001/wpqs/servlet/COM.qpart.Attachment?PartNumber=63.R0034.1DL
R1894 = 1KR2J-1-GP: CHIP RES 1K J 1/16W 0402; Belong: POP; Category: LED_WOL; GREENDFACTOR: R2_SA;HF_SA;G_SA;; POP?: NOPOP; Package Type: SMD-RG; Part Number: 63.10234.1DL; Part Type: SMD-RG; SPEC: http://wpqssvr.wistron.com.tw:7001/wpqs/servlet/COM.qpart.Attachment?PartNumber=63.10234.1DL
R1895 = 10KR2J-3-GP: CHIP RES 10K J 1/16W 0402; Belong: POP; Category: LED_WOL; GREENDFACTOR: R2_SA;HF_SA;G_SA;; MP_POP?: N/A; Module: Internal Connector; POP?: NOPOP; Package Type: SMD-RG; Part Number: 63.10334.1DL; SPEC: http://wpqssvr.wistron.com.tw:7001/wpqs/servlet/COM.qpart.Attachment?PartNumber=63.10334.1DL
R1896 R1897 = 0R2J-2-GP: CHIP RES 0 J 1/16W 0402; Belong: POP; Category: LED_WOL; GREENDFACTOR: R2_SA;HF_SA;G_SA;; Part Number: 63.R0034.1DL; Part Type: SMD-RG; SPEC: http://wpqssvr.wistron.com.tw:7001/wpqs/servlet/COM.qpart.Attachment?PartNumber=63.R0034.1DL
R1906 R1907 = 0R2J-2-GP: CHIP RES 0 J 1/16W 0402; Belong: POP; Category: LED_WOL; GREENDFACTOR: R2_SA;HF_SA;G_SA;; POP?: NOPOP; Part Number: 63.R0034.1DL; Part Type: SMD-RG; SPEC: http://wpqssvr.wistron.com.tw:7001/wpqs/servlet/COM.qpart.Attachment?PartNumber=63.R0034.1DL
R1908 R1914 = 0R2J-2-GP: CHIP RES 0 J 1/16W 0402; Belong: POP; Category: LED_WOL; GREENDFACTOR: R_SA;HF_SA;G_SA;; MP_POP?: N/A; Module: Internal Connector; POP?: NOPOP; Part Number: 63.R0034.1DL; Part Type: SMD-RG; SPEC: http://wpqssvr.wistron.com.tw:7001/wpqs/servlet/COM.qpart.Attachment?PartNumber=63.R0034.1DL
R1912 = 0R2J-2-GP: CHIP RES 0 J 1/16W 0402; Category: BMC; DESCRIPTIO: CHIP RES 0 J 1/16W 0402; GREENDFACTOR: R2_SA;HF_SA;G_SA;; Package Type: SMD-RG; Part Number: 63.R0034.1DL; Part Type: SMD-RG; SPEC: http://wpqssvr.wistron.com.tw:7001/wpqs/servlet/COM.qpart.Attachment?PartNumber=63.R0034.1DL; VENDORPARTNUMBER: RM04JTN0/RTT02000JTH/RR0510X-000-XN/RC0402JR-070RL/WR04X000 PTL
R1913 = 10KR2J-3-GP: CHIP RES 10K J 1/16W 0402; Belong: POP; Category: LED_WOL; GREENDFACTOR: R2_SA;HF_SA;G_SA;; MP_POP?: N/A; Module: Internal Connector; Package Type: SMD-RG; Part Number: 63.10334.1DL; SPEC: http://wpqssvr.wistron.com.tw:7001/wpqs/servlet/COM.qpart.Attachment?PartNumber=63.10334.1DL
RESET1 = SW-TACT-4P-184-GP: SW TACT 4P ST DTS-65K-Q, PA6T & PA66; GREENDFACTOR: R2_C;; Part Number: 022.40001.0441; Part Type: DISCRET-GB1; SPEC: http://wpqssvr.wistron.com.tw:7001/wpqs/servlet/COM.qpart.Attachment?PartNumber=022.40001.0441
U102 = 74LVC2G74GD-GP: IC FI-FO 74LVC2G74GD XSON8U 8P; Belong: POP; Category: LED_WOL; GREENDFACTOR: R2_SA;; Part Number: 73.02G74.0H3; Part Type: DISCRET-G6; SPEC: http://wpqssvr.wistron.com.tw:7001/wpqs/servlet/COM.qpart.Attachment?PartNumber=73.02G74.0H3
U103 = 74AHC1G32DBVR-GP: IC CMOS SN74AHC1G32DBVR SOT23-; Belong: POP; Category: LED_WOL; GREENDFACTOR: R_SA;; Module: Reset/PWRGD Logic; Package Type: DISCRET-G; Part Number: 73.01G32.CAG; SPEC: http://wpqssvr.wistron.com.tw:7001/wpqs/servlet/COM.qpart.Attachment?PartNumber=73.01G32.CAG
U170 = TSLVC07APW-GP: IC CMOS 74LVC07APW TSSOP 14P; GREENDFACTOR: R2_SA;HF_SA;; Part Number: 73.07407.DHB; Part Type: TTL-G; SPEC: http://wpqssvr.wistron.com.tw:7001/wpqs/servlet/COM.qpart.Attachment?PartNumber=73.07407.DHB
U171 U173 = SNLVC1G126DCKR-GP: IC CMOS SN74LVC1G126DCKR SC70; GREENDFACTOR: R2_SA;HF_SA;; POP?: NOPOP; Package Type: TTL-G; Part Number: 73.1G126.DHG; SPEC: http://wpqssvr.wistron.com.tw:7001/wpqs/servlet/COM.qpart.Attachment?PartNumber=73.1G126.DHG
U172 U174 = SNLVC1G08DCKRG4-GP: IC CMOS SN74LVC1G08DCKRG4 DCK; Alternate: 73.01G08.CAH,73.01G08.L04,73.01G08.DAH; Category: CPU SIDE BAND; DESCRIPTIO: IC CMOS SN74LVC1G08DCKRG4 DCK; GREENDFACTOR: R2_SA;HF_SA;G_SA;; Package Type: TTL-G; Part Number: 73.01G08.DHG; Part Type: TTL-G; SPEC: http://wpqssvr.wistron.com.tw:7001/wpqs/servlet/COM.qpart.Attachment?PartNumber=73.01G08.DHG; VENDORPARTNUMBER: SN74LVC1G08DCKRG4
U175 = TSLVC14APW-2-GP: IC CMOS 74LVC14APW TSSOP 14P; Alternate: 73.07414.EHB; Category: Logic; DESCRIPTIO: IC CMOS 74LVC14APW TSSOP 14P; GREENDFACTOR: R2_SA;; Package Type: TTL-G; Part Number: 73.07414.FHB; Part Type: TTL-G; SPEC: http://wpqssvr.wistron.com.tw:7001/wpqs/servlet/COM.qpart.Attachment?PartNumber=73.07414.FHB; VENDORPARTNUMBER: 74LVC14APW

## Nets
GND: C41.2 C81.2 C96.2 C222.2 C223.2 C224.2 C225.2 C226.2 C227.2 C228.2 C229.2 C230.2 C231.2 C232.2 C233.2 C234.2 C235.2 C236.2 C237.2 C238.2 C239.2 C240.2 C241.2 C242.2 C243.2 C244.2 C245.2 C246.2 C247.2 C248.2 C249.2 C250.2 C251.2 C252.2 C253.2 C254.2 C255.2 C256.2 C277.2 C278.2 C279.2 C315.2 C370.2 C993.2 C1002.2 C1003.2 CPU1.A5(VSS) CPU1.A7(VSS) CPU1.A23(VSS) CPU1.A37(VSS) CPU1.A39(VSS) CPU1.A41(VSS) CPU1.A43(VSS) CPU1.A45(VSS) CPU1.A47(VSS) CPU1.A49(VSS) CPU1.A51(VSS) CPU1.AA3(VSS) CPU1.AA7(VSS) CPU1.AA25(VSS) CPU1.AA29(VSS) CPU1.AA31(VSS) CPU1.AA39(VSS) CPU1.AA55(VSS) CPU1.AB12(VSS) CPU1.AB36(VSS) CPU1.AB40(VSS) CPU1.AB42(VSS) CPU1.AC7(VSS) CPU1.AC9(VSS) CPU1.AC11(VSS) CPU1.AC29(VSS) CPU1.AD4(VSS) CPU1.AD6(VSS) CPU1.AD8(VSS) CPU1.AD10(VSS) CPU1.AD12(VSS) CPU1.AD36(VSS) CPU1.AD40(VSS) CPU1.AD42(VSS) CPU1.AD44(VSS) CPU1.AD46(VSS) CPU1.AD48(VSS) CPU1.AD50(VSS) CPU1.AD52(VSS) CPU1.AE13(VSS) CPU1.AE15(VSS) CPU1.AE19(VSS) CPU1.AE23(VSS) CPU1.AE27(VSS) CPU1.AE29(VSS) CPU1.AE33(VSS) CPU1.AE35(VSS) CPU1.AE39(VSS) CPU1.AE41(VSS) CPU1.AE43(VSS) CPU1.AE47(VSS) CPU1.AE49(VSS) CPU1.AE51(VSS) CPU1.AE53(VSS) CPU1.AF2(VSS) CPU1.AF4(VSS) CPU1.AF6(VSS) CPU1.AF8(VSS) CPU1.AF10(VSS) CPU1.AF16(VSS) CPU1.AF18(VSS) CPU1.AF20(VSS) CPU1.AF22(VSS) CPU1.AF24(VSS) CPU1.AF26(VSS) CPU1.AF28(VSS) CPU1.AF30(VSS) CPU1.AF32(VSS) CPU1.AF34(VSS) CPU1.AF36(VSS) CPU1.AF38(VSS) CPU1.AF40(VSS) CPU1.AF54(VSS) CPU1.AF56(VSS) CPU1.AG11(VSS) CPU1.AG13(VSS) CPU1.AG17(VSS) CPU1.AG19(VSS) CPU1.AG21(VSS) CPU1.AG25(VSS) CPU1.AG31(VSS) CPU1.AG37(VSS) CPU1.AG43(VSS) CPU1.AG55(VSS) CPU1.AG57(VSS) CPU1.AH2(VSS) CPU1.AH6(VSS) CPU1.AH14(VSS) CPU1.AH58(VSS) CPU1.AJ11(VSS) CPU1.AJ17(VSS) CPU1.AK4(VSS) CPU1.AK6(VSS) CPU1.AK16(VSS) CPU1.AK42(VSS) CPU1.AK44(VSS) CPU1.AK46(VSS) CPU1.AK48(VSS) CPU1.AK50(VSS) CPU1.AK52(VSS) CPU1.AL11(VSS) CPU1.AL43(VSS) CPU1.AL45(VSS) CPU1.AL47(VSS) CPU1.AL49(VSS) CPU1.AL51(VSS) CPU1.AL53(VSS) CPU1.AM2(VSS) CPU1.AM4(VSS) CPU1.AM6(VSS) CPU1.AM8(VSS) CPU1.AM10(VSS) CPU1.AM12(VSS) CPU1.AM14(VSS) CPU1.AM16(VSS) CPU1.AM56(VSS) CPU1.AN1(VSS) CPU1.AN3(VSS) CPU1.AN5(VSS) CPU1.AN7(VSS) CPU1.AN9(VSS) CPU1.AN13(VSS) CPU1.AN15(VSS) CPU1.AN55(VSS) CPU1.AN57(VSS) CPU1.AP42(VSS) CPU1.AP44(VSS) CPU1.AP58(VSS) CPU1.AT44(VSS) CPU1.AT46(VSS) CPU1.AT48(VSS) CPU1.AT50(VSS) CPU1.AT52(VSS) CPU1.AU45(VSS) CPU1.AU47(VSS) CPU1.AU49(VSS) CPU1.AU51(VSS) CPU1.AU53(VSS) CPU1.AV42(VSS) CPU1.AV54(VSS) CPU1.AV56(VSS) CPU1.AW3(VSS) CPU1.AW5(VSS) CPU1.AW7(VSS) CPU1.AW9(VSS) CPU1.AW11(VSS) CPU1.AW13(VSS) CPU1.AW15(VSS) CPU1.AW17(VSS) CPU1.AW55(VSS) CPU1.AW57(VSS) CPU1.AY2(VSS) CPU1.AY4(VSS) CPU1.AY6(VSS) CPU1.AY8(VSS) CPU1.AY10(VSS) CPU1.AY12(VSS) CPU1.AY14(VSS) CPU1.AY16(VSS) CPU1.AY44(VSS) CPU1.B6(VSS) CPU1.B10(VSS) CPU1.B36(VSS) CPU1.B40(VSS) CPU1.B52(VSS) CPU1.BB42(VSS) CPU1.BB46(VSS) CPU1.BB50(VSS) CPU1.BB58(VSS) CPU1.BC45(VSS) CPU1.BC47(VSS) CPU1.BC49(VSS) CPU1.BC51(VSS) CPU1.BC53(VSS) CPU1.BC55(VSS) CPU1.BC57(VSS) CPU1.BD52(VSS) CPU1.BD54(VSS) CPU1.BD56(VSS) CPU1.BE49(VSS) CPU1.BE51(VSS) CPU1.BF2(VSS) CPU1.BF4(VSS) CPU1.BF6(VSS) CPU1.BF8(VSS) CPU1.BF10(VSS) CPU1.BF12(VSS) CPU1.BF14(VSS) CPU1.BF16(VSS) CPU1.BF42(VSS) CPU1.BG3(VSS) CPU1.BG5(VSS) CPU1.BG7(VSS) CPU1.BG9(VSS) CPU1.BG11(VSS) CPU1.BG13(VSS) CPU1.BG15(VSS) CPU1.BG17(VSS) CPU1.BG45(VSS) CPU1.BG47(VSS) CPU1.BH58(VSS) CPU1.BJ55(VSS) CPU1.BJ57(VSS) CPU1.BK42(VSS) CPU1.BK46(VSS) CPU1.BK48(VSS) CPU1.BK50(VSS) CPU1.BK52(VSS) CPU1.BK54(VSS) CPU1.BL45(VSS) CPU1.BL49(VSS) CPU1.BL57(VSS) CPU1.BN43(VSS) CPU1.BN57(VSS) CPU1.BP4(VSS) CPU1.BP6(VSS) CPU1.BP8(VSS) CPU1.BP12(VSS) CPU1.BP14(VSS) CPU1.BP58(VSS) CPU1.BR1(VSS) CPU1.BR3(VSS) CPU1.BR5(VSS) CPU1.BR7(VSS) CPU1.BR9(VSS) CPU1.BR11(VSS) CPU1.BR13(VSS) CPU1.BR15(VSS) CPU1.BR53(VSS) CPU1.BR55(VSS) CPU1.BR57(VSS) CPU1.BT10(VSS) CPU1.BT16(VSS) CPU1.BT42(VSS) CPU1.BT46(VSS) CPU1.BT48(VSS) CPU1.BT50(VSS) CPU1.BT52(VSS) CPU1.BT54(VSS) CPU1.BT56(VSS) CPU1.BU3(VSS) CPU1.BU5(VSS) CPU1.BU45(VSS) CPU1.BU47(VSS) CPU1.BU51(VSS) CPU1.BV10(VSS) CPU1.BV16(VSS) CPU1.BW5(VSS) CPU1.BW7(VSS) CPU1.BW15(VSS) CPU1.BW17(VSS) CPU1.BW43(VSS) CPU1.BY8(VSS) CPU1.BY10(VSS) CPU1.BY28(VSS) CPU1.BY32(VSS) CPU1.BY58(VSS) CPU1.C5(VSS) CPU1.C33(VSS) CPU1.C55(VSS) CPU1.CA5(VSS) CPU1.CA13(VSS) CPU1.CA15(VSS) CPU1.CA17(VSS) CPU1.CA19(VSS) CPU1.CA21(VSS) CPU1.CA23(VSS) CPU1.CA25(VSS) CPU1.CA27(VSS) CPU1.CA29(VSS) CPU1.CA31(VSS) CPU1.CA33(VSS) CPU1.CA35(VSS) CPU1.CA37(VSS) CPU1.CA39(VSS) CPU1.CA41(VSS) CPU1.CA55(VSS) CPU1.CA57(VSS) CPU1.CB2(VSS) CPU1.CB10(VSS) CPU1.CB12(VSS) CPU1.CB14(VSS) CPU1.CB30(VSS) CPU1.CB34(VSS) CPU1.CB36(VSS) CPU1.CB38(VSS) CPU1.CB40(VSS) CPU1.CB42(VSS) CPU1.CB44(VSS) CPU1.CB46(VSS) CPU1.CB48(VSS) CPU1.CB50(VSS) CPU1.CB52(VSS) CPU1.CB54(VSS) CPU1.CB56(VSS) CPU1.CC3(VSS) CPU1.CC5(VSS) CPU1.CC7(VSS) CPU1.CC9(VSS) CPU1.CC11(VSS) CPU1.CC33(VSS) CPU1.CC43(VSS) CPU1.CC45(VSS) CPU1.CC47(VSS) CPU1.CC49(VSS) CPU1.CD4(VSS) CPU1.CD6(VSS) CPU1.CD8(VSS) CPU1.CD12(VSS) CPU1.CD40(VSS) CPU1.CE7(VSS) CPU1.CE15(VSS) CPU1.CE33(VSS) CPU1.CE43(VSS) CPU1.CE45(VSS) CPU1.CF10(VSS) CPU1.CF12(VSS) CPU1.CF28(VSS) CPU1.CF32(VSS) CPU1.CG5(VSS) CPU1.CG7(VSS) CPU1.CG27(VSS) CPU1.CG29(VSS) CPU1.CG31(VSS) CPU1.CG33(VSS) CPU1.CG35(VSS) CPU1.CG37(VSS) CPU1.CG39(VSS) CPU1.CG43(VSS) CPU1.CG45(VSS) CPU1.CG53(VSS) CPU1.CH12(VSS) CPU1.CH30(VSS) CPU1.CH34(VSS) CPU1.CH36(VSS) CPU1.CH38(VSS) CPU1.CH40(VSS) CPU1.CH42(VSS) CPU1.CH44(VSS) CPU1.CH46(VSS) CPU1.CH48(VSS) CPU1.CH50(VSS) CPU1.CH52(VSS) CPU1.CH54(VSS) CPU1.CH56(VSS) CPU1.CJ3(VSS) CPU1.CJ7(VSS) CPU1.CJ15(VSS) CPU1.CJ33(VSS) CPU1.CJ41(VSS) CPU1.CJ43(VSS) CPU1.CJ45(VSS) CPU1.CJ47(VSS) CPU1.CJ49(VSS) CPU1.CJ51(VSS) CPU1.CK4(VSS) CPU1.CK12(VSS) CPU1.CK40(VSS) CPU1.CK52(VSS) CPU1.CK54(VSS) CPU1.CL7(VSS) CPU1.CL9(VSS) CPU1.CL11(VSS) CPU1.CL15(VSS) CPU1.CM6(VSS) CPU1.CM8(VSS) CPU1.CM10(VSS) CPU1.CM28(VSS) CPU1.CM32(VSS) CPU1.CM40(VSS) CPU1.CM52(VSS) CPU1.CM54(VSS) CPU1.CN3(VSS) CPU1.CN5(VSS) CPU1.CN7(VSS) CPU1.CN11(VSS) CPU1.CN13(VSS) CPU1.CN27(VSS) CPU1.CN29(VSS) CPU1.CN31(VSS) CPU1.CN33(VSS) CPU1.CN35(VSS) CPU1.CN37(VSS) CPU1.CN39(VSS) CPU1.CN53(VSS) CPU1.CN55(VSS) CPU1.CN57(VSS) CPU1.CP4(VSS) CPU1.CP12(VSS) CPU1.CP14(VSS) CPU1.CP30(VSS) CPU1.CP34(VSS) CPU1.CP36(VSS) CPU1.CP38(VSS) CPU1.CP42(VSS) CPU1.CP44(VSS) CPU1.CP46(VSS) CPU1.CP48(VSS) CPU1.CP50(VSS) CPU1.CP56(VSS) CPU1.CR7(VSS) CPU1.CR9(VSS) CPU1.CR33(VSS) CPU1.CR41(VSS) CPU1.CR45(VSS) CPU1.CR47(VSS) CPU1.CR49(VSS) CPU1.CT2(VSS) CPU1.CT12(VSS) CPU1.CT40(VSS) CPU1.CU1(VSS) CPU1.CU7(VSS) CPU1.CU15(VSS) CPU1.CU33(VSS) CPU1.CV6(VSS) CPU1.CV12(VSS) CPU1.CV28(VSS) CPU1.CV32(VSS) CPU1.CV40(VSS) CPU1.CV54(VSS) CPU1.CV58(VSS) CPU1.CW1(VSS) CPU1.CW5(VSS) CPU1.CW7(VSS) CPU1.CW15(VSS) CPU1.CW27(VSS) CPU1.CW29(VSS) CPU1.CW31(VSS) CPU1.CW33(VSS) CPU1.CW35(VSS) CPU1.CW37(VSS) CPU1.CW39(VSS) CPU1.CW53(VSS) CPU1.CW55(VSS) CPU1.CW57(VSS) CPU1.CY2(VSS) CPU1.CY4(VSS) CPU1.CY8(VSS) CPU1.CY10(VSS) CPU1.CY12(VSS) CPU1.CY30(VSS) CPU1.CY34(VSS) CPU1.CY36(VSS) CPU1.CY38(VSS) CPU1.CY42(VSS) CPU1.CY44(VSS) CPU1.CY46(VSS) CPU1.CY48(VSS) CPU1.CY50(VSS) CPU1.CY52(VSS) CPU1.D4(VSS) CPU1.D10(VSS) CPU1.D24(VSS) CPU1.D36(VSS) CPU1.D40(VSS) CPU1.DA3(VSS) CPU1.DA9(VSS) CPU1.DA27(VSS) CPU1.DA35(VSS) CPU1.DA41(VSS) CPU1.DA43(VSS) CPU1.DA45(VSS) CPU1.DA47(VSS) CPU1.DA49(VSS) CPU1.DA51(VSS) CPU1.DA53(VSS) CPU1.DA55(VSS) CPU1.DB6(VSS) CPU1.DB12(VSS) CPU1.DB34(VSS) CPU1.DB40(VSS) CPU1.DB58(VSS) CPU1.DC5(VSS) CPU1.DC53(VSS) CPU1.DC55(VSS) CPU1.DD6(VSS) CPU1.DD10(VSS) CPU1.DD12(VSS) CPU1.DD34(VSS) CPU1.DD38(VSS) CPU1.DD40(VSS) CPU1.DE7(VSS) CPU1.DE15(VSS) CPU1.DE35(VSS) CPU1.DF8(VSS) CPU1.DF12(VSS) CPU1.DF40(VSS) CPU1.DF42(VSS) CPU1.DF44(VSS) CPU1.DF46(VSS) CPU1.DF48(VSS) CPU1.DF50(VSS) CPU1.DF52(VSS) CPU1.E1(VSS) CPU1.E3(VSS) CPU1.E39(VSS) CPU1.E41(VSS) CPU1.F2(VSS) CPU1.F4(VSS) CPU1.F30(VSS) CPU1.F32(VSS) CPU1.F36(VSS) CPU1.F42(VSS) CPU1.F44(VSS) CPU1.F48(VSS) CPU1.F50(VSS) CPU1.G1(VSS) CPU1.G5(VSS) CPU1.G9(VSS) CPU1.G23(VSS) CPU1.G27(VSS) CPU1.G33(VSS) CPU1.G35(VSS) CPU1.G39(VSS) CPU1.G41(VSS) CPU1.G45(VSS) CPU1.G47(VSS) CPU1.G49(VSS) CPU1.G51(VSS) CPU1.G53(VSS) CPU1.G57(VSS) CPU1.H6(VSS) CPU1.H8(VSS) CPU1.H24(VSS) CPU1.H26(VSS) CPU1.H28(VSS) CPU1.H30(VSS) CPU1.H32(VSS) CPU1.H34(VSS) CPU1.H36(VSS) CPU1.H40(VSS) CPU1.H54(VSS) CPU1.J3(VSS) CPU1.J5(VSS) CPU1.J7(VSS) CPU1.J25(VSS) CPU1.J29(VSS) CPU1.J31(VSS) CPU1.J37(VSS) CPU1.J55(VSS) CPU1.K10(VSS) CPU1.K36(VSS) CPU1.K40(VSS) CPU1.L5(VSS) CPU1.L29(VSS) CPU1.L39(VSS) CPU1.L41(VSS) CPU1.M2(VSS) CPU1.M10(VSS) CPU1.M36(VSS) CPU1.M42(VSS) CPU1.M44(VSS) CPU1.M46(VSS) CPU1.M48(VSS) CPU1.M50(VSS) CPU1.M52(VSS) CPU1.N5(VSS) CPU1.N23(VSS) CPU1.N27(VSS) CPU1.N29(VSS) CPU1.N33(VSS) CPU1.N35(VSS) CPU1.N37(VSS) CPU1.N39(VSS) CPU1.N43(VSS) CPU1.N45(VSS) CPU1.N47(VSS) CPU1.N49(VSS) CPU1.N51(VSS) CPU1.N53(VSS) CPU1.P10(VSS) CPU1.P24(VSS) CPU1.P26(VSS) CPU1.P28(VSS) CPU1.P30(VSS) CPU1.P32(VSS) CPU1.P34(VSS) CPU1.P38(VSS) CPU1.P40(VSS) CPU1.P54(VSS) CPU1.P56(VSS) CPU1.R5(VSS) CPU1.R9(VSS) CPU1.R11(VSS) CPU1.R25(VSS) CPU1.R29(VSS) CPU1.R31(VSS) CPU1.R39(VSS) CPU1.R55(VSS) CPU1.T4(VSS) CPU1.T6(VSS) CPU1.T8(VSS) CPU1.T36(VSS) CPU1.T42(VSS) CPU1.U3(VSS) CPU1.U7(VSS) CPU1.U29(VSS) CPU1.U39(VSS) CPU1.U41(VSS) CPU1.U43(VSS) CPU1.V10(VSS) CPU1.V12(VSS) CPU1.V36(VSS) CPU1.V44(VSS) CPU1.V46(VSS) CPU1.V48(VSS) CPU1.V50(VSS) CPU1.V52(VSS) CPU1.W7(VSS) CPU1.W23(VSS) CPU1.W27(VSS) CPU1.W33(VSS) CPU1.W35(VSS) CPU1.W39(VSS) CPU1.W43(VSS) CPU1.W45(VSS) CPU1.W47(VSS) CPU1.W49(VSS) CPU1.W51(VSS) CPU1.W53(VSS) CPU1.Y4(VSS) CPU1.Y12(VSS) CPU1.Y24(VSS) CPU1.Y26(VSS) CPU1.Y28(VSS) CPU1.Y30(VSS) CPU1.Y32(VSS) CPU1.Y34(VSS) CPU1.Y36(VSS) CPU1.Y42(VSS) CPU1.Y56(VSS) CPU2.A5(VSS) CPU2.A7(VSS) CPU2.A23(VSS) CPU2.A37(VSS) CPU2.A39(VSS) CPU2.A41(VSS) CPU2.A43(VSS) CPU2.A45(VSS) CPU2.A47(VSS) CPU2.A49(VSS) CPU2.A51(VSS) CPU2.AA3(VSS) CPU2.AA7(VSS) CPU2.AA25(VSS) CPU2.AA29(VSS) CPU2.AA31(VSS) CPU2.AA39(VSS) CPU2.AA55(VSS) CPU2.AB12(VSS) CPU2.AB36(VSS) CPU2.AB40(VSS) CPU2.AB42(VSS) CPU2.AC7(VSS) CPU2.AC9(VSS) CPU2.AC11(VSS) CPU2.AC29(VSS) CPU2.AD4(VSS) CPU2.AD6(VSS) CPU2.AD8(VSS) CPU2.AD10(VSS) CPU2.AD12(VSS) CPU2.AD36(VSS) CPU2.AD40(VSS) CPU2.AD42(VSS) CPU2.AD44(VSS) CPU2.AD46(VSS) CPU2.AD48(VSS) CPU2.AD50(VSS) CPU2.AD52(VSS) CPU2.AE13(VSS) CPU2.AE15(VSS) CPU2.AE19(VSS) CPU2.AE23(VSS) CPU2.AE27(VSS) CPU2.AE29(VSS) CPU2.AE33(VSS) CPU2.AE35(VSS) CPU2.AE39(VSS) CPU2.AE41(VSS) CPU2.AE43(VSS) CPU2.AE47(VSS) CPU2.AE49(VSS) CPU2.AE51(VSS) CPU2.AE53(VSS) CPU2.AF2(VSS) CPU2.AF4(VSS) CPU2.AF6(VSS) CPU2.AF8(VSS) CPU2.AF10(VSS) CPU2.AF16(VSS) CPU2.AF18(VSS) CPU2.AF20(VSS) CPU2.AF22(VSS) CPU2.AF24(VSS) CPU2.AF26(VSS) CPU2.AF28(VSS) CPU2.AF30(VSS) CPU2.AF32(VSS) CPU2.AF34(VSS) CPU2.AF36(VSS) CPU2.AF38(VSS) CPU2.AF40(VSS) CPU2.AF54(VSS) CPU2.AF56(VSS) CPU2.AG11(VSS) CPU2.AG13(VSS) CPU2.AG17(VSS) CPU2.AG19(VSS) CPU2.AG21(VSS) CPU2.AG25(VSS) CPU2.AG31(VSS) CPU2.AG37(VSS) CPU2.AG43(VSS) CPU2.AG55(VSS) CPU2.AG57(VSS) CPU2.AH2(VSS) CPU2.AH6(VSS) CPU2.AH14(VSS) CPU2.AH58(VSS) CPU2.AJ11(VSS) CPU2.AJ17(VSS) CPU2.AK4(VSS) CPU2.AK6(VSS) CPU2.AK16(VSS) CPU2.AK42(VSS) CPU2.AK44(VSS) CPU2.AK46(VSS) CPU2.AK48(VSS) CPU2.AK50(VSS) CPU2.AK52(VSS) CPU2.AL11(VSS) CPU2.AL43(VSS) CPU2.AL45(VSS) CPU2.AL47(VSS) CPU2.AL49(VSS) CPU2.AL51(VSS) CPU2.AL53(VSS) CPU2.AM2(VSS) CPU2.AM4(VSS) CPU2.AM6(VSS) CPU2.AM8(VSS) CPU2.AM10(VSS) CPU2.AM12(VSS) CPU2.AM14(VSS) CPU2.AM16(VSS) CPU2.AM56(VSS) CPU2.AN1(VSS) CPU2.AN3(VSS) CPU2.AN5(VSS) CPU2.AN7(VSS) CPU2.AN9(VSS) CPU2.AN13(VSS) CPU2.AN15(VSS) CPU2.AN55(VSS) CPU2.AN57(VSS) CPU2.AP42(VSS) CPU2.AP44(VSS) CPU2.AP58(VSS) CPU2.AT44(VSS) CPU2.AT46(VSS) CPU2.AT48(VSS) CPU2.AT50(VSS) CPU2.AT52(VSS) CPU2.AU45(VSS) CPU2.AU47(VSS) CPU2.AU49(VSS) CPU2.AU51(VSS) CPU2.AU53(VSS) CPU2.AV42(VSS) CPU2.AV54(VSS) CPU2.AV56(VSS) CPU2.AW3(VSS) CPU2.AW5(VSS) CPU2.AW7(VSS) CPU2.AW9(VSS) CPU2.AW11(VSS) CPU2.AW13(VSS) CPU2.AW15(VSS) CPU2.AW17(VSS) CPU2.AW55(VSS) CPU2.AW57(VSS) CPU2.AY2(VSS) CPU2.AY4(VSS) CPU2.AY6(VSS) CPU2.AY8(VSS) CPU2.AY10(VSS) CPU2.AY12(VSS) CPU2.AY14(VSS) CPU2.AY16(VSS) CPU2.AY44(VSS) CPU2.B6(VSS) CPU2.B10(VSS) CPU2.B36(VSS) CPU2.B40(VSS) CPU2.B52(VSS) CPU2.BB42(VSS) CPU2.BB46(VSS) CPU2.BB50(VSS) CPU2.BB58(VSS) CPU2.BC45(VSS) CPU2.BC47(VSS) CPU2.BC49(VSS) CPU2.BC51(VSS) CPU2.BC53(VSS) CPU2.BC55(VSS) CPU2.BC57(VSS) CPU2.BD52(VSS) CPU2.BD54(VSS) CPU2.BD56(VSS) CPU2.BE49(VSS) CPU2.BE51(VSS) CPU2.BF2(VSS) CPU2.BF4(VSS) CPU2.BF6(VSS) CPU2.BF8(VSS) CPU2.BF10(VSS) CPU2.BF12(VSS) CPU2.BF14(VSS) CPU2.BF16(VSS) CPU2.BF42(VSS) CPU2.BG3(VSS) CPU2.BG5(VSS) CPU2.BG7(VSS) CPU2.BG9(VSS) CPU2.BG11(VSS) CPU2.BG13(VSS) CPU2.BG15(VSS) CPU2.BG17(VSS) CPU2.BG45(VSS) CPU2.BG47(VSS) CPU2.BH58(VSS) CPU2.BJ55(VSS) CPU2.BJ57(VSS) CPU2.BK42(VSS) CPU2.BK46(VSS) CPU2.BK48(VSS) CPU2.BK50(VSS) CPU2.BK52(VSS) CPU2.BK54(VSS) CPU2.BL45(VSS) CPU2.BL49(VSS) CPU2.BL57(VSS) CPU2.BN43(VSS) CPU2.BN57(VSS) CPU2.BP4(VSS) CPU2.BP6(VSS) CPU2.BP8(VSS) CPU2.BP12(VSS) CPU2.BP14(VSS) CPU2.BP58(VSS) CPU2.BR1(VSS) CPU2.BR3(VSS) CPU2.BR5(VSS) CPU2.BR7(VSS) CPU2.BR9(VSS) CPU2.BR11(VSS) CPU2.BR13(VSS) CPU2.BR15(VSS) CPU2.BR53(VSS) CPU2.BR55(VSS) CPU2.BR57(VSS) CPU2.BT10(VSS) CPU2.BT16(VSS) CPU2.BT42(VSS) CPU2.BT46(VSS) CPU2.BT48(VSS) CPU2.BT50(VSS) CPU2.BT52(VSS) CPU2.BT54(VSS) CPU2.BT56(VSS) CPU2.BU3(VSS) CPU2.BU5(VSS) CPU2.BU45(VSS) CPU2.BU47(VSS) CPU2.BU51(VSS) CPU2.BV10(VSS) CPU2.BV16(VSS) CPU2.BW5(VSS) CPU2.BW7(VSS) CPU2.BW15(VSS) CPU2.BW17(VSS) CPU2.BW43(VSS) CPU2.BY8(VSS) CPU2.BY10(VSS) CPU2.BY28(VSS) CPU2.BY32(VSS) CPU2.BY58(VSS) CPU2.C5(VSS) CPU2.C33(VSS) CPU2.C55(VSS) CPU2.CA5(VSS) CPU2.CA13(VSS) CPU2.CA15(VSS) CPU2.CA17(VSS) CPU2.CA19(VSS) CPU2.CA21(VSS) CPU2.CA23(VSS) CPU2.CA25(VSS) CPU2.CA27(VSS) CPU2.CA29(VSS) CPU2.CA31(VSS) CPU2.CA33(VSS) CPU2.CA35(VSS) CPU2.CA37(VSS) CPU2.CA39(VSS) CPU2.CA41(VSS) CPU2.CA55(VSS) CPU2.CA57(VSS) CPU2.CB2(VSS) CPU2.CB10(VSS) CPU2.CB12(VSS) CPU2.CB14(VSS) CPU2.CB30(VSS) CPU2.CB34(VSS) CPU2.CB36(VSS) CPU2.CB38(VSS) CPU2.CB40(VSS) CPU2.CB42(VSS) CPU2.CB44(VSS) CPU2.CB46(VSS) CPU2.CB48(VSS) CPU2.CB50(VSS) CPU2.CB52(VSS) CPU2.CB54(VSS) CPU2.CB56(VSS) CPU2.CC3(VSS) CPU2.CC5(VSS) CPU2.CC7(VSS) CPU2.CC9(VSS) CPU2.CC11(VSS) CPU2.CC33(VSS) CPU2.CC43(VSS) CPU2.CC45(VSS) CPU2.CC47(VSS) CPU2.CC49(VSS) CPU2.CD4(VSS) CPU2.CD6(VSS) CPU2.CD8(VSS) CPU2.CD12(VSS) CPU2.CD40(VSS) CPU2.CE7(VSS) CPU2.CE15(VSS) CPU2.CE33(VSS) CPU2.CE43(VSS) CPU2.CE45(VSS) CPU2.CF10(VSS) CPU2.CF12(VSS) CPU2.CF28(VSS) CPU2.CF32(VSS) CPU2.CG5(VSS) CPU2.CG7(VSS) CPU2.CG27(VSS) CPU2.CG29(VSS) CPU2.CG31(VSS) CPU2.CG33(VSS) CPU2.CG35(VSS) CPU2.CG37(VSS) CPU2.CG39(VSS) CPU2.CG43(VSS) CPU2.CG45(VSS) CPU2.CG53(VSS) CPU2.CH12(VSS) CPU2.CH30(VSS) CPU2.CH34(VSS) CPU2.CH36(VSS) CPU2.CH38(VSS) CPU2.CH40(VSS) CPU2.CH42(VSS) CPU2.CH44(VSS) CPU2.CH46(VSS) CPU2.CH48(VSS) CPU2.CH50(VSS) CPU2.CH52(VSS) CPU2.CH54(VSS) CPU2.CH56(VSS) CPU2.CJ3(VSS) CPU2.CJ7(VSS) CPU2.CJ15(VSS) CPU2.CJ33(VSS) CPU2.CJ41(VSS) CPU2.CJ43(VSS) CPU2.CJ45(VSS) CPU2.CJ47(VSS) CPU2.CJ49(VSS) CPU2.CJ51(VSS) CPU2.CK4(VSS) CPU2.CK12(VSS) CPU2.CK40(VSS) CPU2.CK52(VSS) CPU2.CK54(VSS) CPU2.CL7(VSS) CPU2.CL9(VSS) CPU2.CL11(VSS) CPU2.CL15(VSS) CPU2.CM6(VSS) CPU2.CM8(VSS) CPU2.CM10(VSS) CPU2.CM28(VSS) CPU2.CM32(VSS) CPU2.CM40(VSS) CPU2.CM52(VSS) CPU2.CM54(VSS) CPU2.CN3(VSS) CPU2.CN5(VSS) CPU2.CN7(VSS) CPU2.CN11(VSS) CPU2.CN13(VSS) CPU2.CN27(VSS) CPU2.CN29(VSS) CPU2.CN31(VSS) CPU2.CN33(VSS) CPU2.CN35(VSS) CPU2.CN37(VSS) CPU2.CN39(VSS) CPU2.CN53(VSS) CPU2.CN55(VSS) CPU2.CN57(VSS) CPU2.CP4(VSS) CPU2.CP12(VSS) CPU2.CP14(VSS) CPU2.CP30(VSS) CPU2.CP34(VSS) CPU2.CP36(VSS) CPU2.CP38(VSS) CPU2.CP42(VSS) CPU2.CP44(VSS) CPU2.CP46(VSS) CPU2.CP48(VSS) CPU2.CP50(VSS) CPU2.CP56(VSS) CPU2.CR7(VSS) CPU2.CR9(VSS) CPU2.CR33(VSS) CPU2.CR41(VSS) CPU2.CR45(VSS) CPU2.CR47(VSS) CPU2.CR49(VSS) CPU2.CT2(VSS) CPU2.CT12(VSS) CPU2.CT40(VSS) CPU2.CU1(VSS) CPU2.CU7(VSS) CPU2.CU15(VSS) CPU2.CU33(VSS) CPU2.CV6(VSS) CPU2.CV12(VSS) CPU2.CV28(VSS) CPU2.CV32(VSS) CPU2.CV40(VSS) CPU2.CV54(VSS) CPU2.CV58(VSS) CPU2.CW1(VSS) CPU2.CW5(VSS) CPU2.CW7(VSS) CPU2.CW15(VSS) CPU2.CW27(VSS) CPU2.CW29(VSS) CPU2.CW31(VSS) CPU2.CW33(VSS) CPU2.CW35(VSS) CPU2.CW37(VSS) CPU2.CW39(VSS) CPU2.CW53(VSS) CPU2.CW55(VSS) CPU2.CW57(VSS) CPU2.CY2(VSS) CPU2.CY4(VSS) CPU2.CY8(VSS) CPU2.CY10(VSS) CPU2.CY12(VSS) CPU2.CY30(VSS) CPU2.CY34(VSS) CPU2.CY36(VSS) CPU2.CY38(VSS) CPU2.CY42(VSS) CPU2.CY44(VSS) CPU2.CY46(VSS) CPU2.CY48(VSS) CPU2.CY50(VSS) CPU2.CY52(VSS) CPU2.D4(VSS) CPU2.D10(VSS) CPU2.D24(VSS) CPU2.D36(VSS) CPU2.D40(VSS) CPU2.DA3(VSS) CPU2.DA9(VSS) CPU2.DA27(VSS) CPU2.DA35(VSS) CPU2.DA41(VSS) CPU2.DA43(VSS) CPU2.DA45(VSS) CPU2.DA47(VSS) CPU2.DA49(VSS) CPU2.DA51(VSS) CPU2.DA53(VSS) CPU2.DA55(VSS) CPU2.DB6(VSS) CPU2.DB12(VSS) CPU2.DB34(VSS) CPU2.DB40(VSS) CPU2.DB58(VSS) CPU2.DC5(VSS) CPU2.DC53(VSS) CPU2.DC55(VSS) CPU2.DD6(VSS) CPU2.DD10(VSS) CPU2.DD12(VSS) CPU2.DD34(VSS) CPU2.DD38(VSS) CPU2.DD40(VSS) CPU2.DE7(VSS) CPU2.DE15(VSS) CPU2.DE35(VSS) CPU2.DF8(VSS) CPU2.DF12(VSS) CPU2.DF40(VSS) CPU2.DF42(VSS) CPU2.DF44(VSS) CPU2.DF46(VSS) CPU2.DF48(VSS) CPU2.DF50(VSS) CPU2.DF52(VSS) CPU2.E1(VSS) CPU2.E3(VSS) CPU2.E39(VSS) CPU2.E41(VSS) CPU2.F2(VSS) CPU2.F4(VSS) CPU2.F30(VSS) CPU2.F32(VSS) CPU2.F36(VSS) CPU2.F42(VSS) CPU2.F44(VSS) CPU2.F48(VSS) CPU2.F50(VSS) CPU2.G1(VSS) CPU2.G5(VSS) CPU2.G9(VSS) CPU2.G23(VSS) CPU2.G27(VSS) CPU2.G33(VSS) CPU2.G35(VSS) CPU2.G39(VSS) CPU2.G41(VSS) CPU2.G45(VSS) CPU2.G47(VSS) CPU2.G49(VSS) CPU2.G51(VSS) CPU2.G53(VSS) CPU2.G57(VSS) CPU2.H6(VSS) CPU2.H8(VSS) CPU2.H24(VSS) CPU2.H26(VSS) CPU2.H28(VSS) CPU2.H30(VSS) CPU2.H32(VSS) CPU2.H34(VSS) CPU2.H36(VSS) CPU2.H40(VSS) CPU2.H54(VSS) CPU2.J3(VSS) CPU2.J5(VSS) CPU2.J7(VSS) CPU2.J25(VSS) CPU2.J29(VSS) CPU2.J31(VSS) CPU2.J37(VSS) CPU2.J55(VSS) CPU2.K10(VSS) CPU2.K36(VSS) CPU2.K40(VSS) CPU2.L5(VSS) CPU2.L29(VSS) CPU2.L39(VSS) CPU2.L41(VSS) CPU2.M2(VSS) CPU2.M10(VSS) CPU2.M36(VSS) CPU2.M42(VSS) CPU2.M44(VSS) CPU2.M46(VSS) CPU2.M48(VSS) CPU2.M50(VSS) CPU2.M52(VSS) CPU2.N5(VSS) CPU2.N23(VSS) CPU2.N27(VSS) CPU2.N29(VSS) CPU2.N33(VSS) CPU2.N35(VSS) CPU2.N37(VSS) CPU2.N39(VSS) CPU2.N43(VSS) CPU2.N45(VSS) CPU2.N47(VSS) CPU2.N49(VSS) CPU2.N51(VSS) CPU2.N53(VSS) CPU2.P10(VSS) CPU2.P24(VSS) CPU2.P26(VSS) CPU2.P28(VSS) CPU2.P30(VSS) CPU2.P32(VSS) CPU2.P34(VSS) CPU2.P38(VSS) CPU2.P40(VSS) CPU2.P54(VSS) CPU2.P56(VSS) CPU2.R5(VSS) CPU2.R9(VSS) CPU2.R11(VSS) CPU2.R25(VSS) CPU2.R29(VSS) CPU2.R31(VSS) CPU2.R39(VSS) CPU2.R55(VSS) CPU2.T4(VSS) CPU2.T6(VSS) CPU2.T8(VSS) CPU2.T36(VSS) CPU2.T42(VSS) CPU2.U3(VSS) CPU2.U7(VSS) CPU2.U29(VSS) CPU2.U39(VSS) CPU2.U41(VSS) CPU2.U43(VSS) CPU2.V10(VSS) CPU2.V12(VSS) CPU2.V36(VSS) CPU2.V44(VSS) CPU2.V46(VSS) CPU2.V48(VSS) CPU2.V50(VSS) CPU2.V52(VSS) CPU2.W7(VSS) CPU2.W23(VSS) CPU2.W27(VSS) CPU2.W33(VSS) CPU2.W35(VSS) CPU2.W39(VSS) CPU2.W43(VSS) CPU2.W45(VSS) CPU2.W47(VSS) CPU2.W49(VSS) CPU2.W51(VSS) CPU2.W53(VSS) CPU2.Y4(VSS) CPU2.Y12(VSS) CPU2.Y24(VSS) CPU2.Y26(VSS) CPU2.Y28(VSS) CPU2.Y30(VSS) CPU2.Y32(VSS) CPU2.Y34(VSS) CPU2.Y36(VSS) CPU2.Y42(VSS) CPU2.Y56(VSS) PWRON1.3(T3) PWRON1.4(T4) R1913.2 RESET1.3(T3) RESET1.4(T4) U102.4(GND) U103.3(GND) U170.1(I) U170.3(I) U170.7(GND) U170.11(I) U170.13(I) U171.3(GND) U172.3(GND) U173.3(GND) U174.3(GND) U175.7(GND) U175.11(I) U175.13(I) ; also on sheet 1 2 3 4 5 6 7 8 9 10 11 12 13 14 15 16 17 18 19 20 21 22 23 24 25 26 27 28 29 30 31 32 33 34 35 36 37 38 39 44 46 47 49 50 51 52 53 54 55 56 57 58 59 60 61 62 63 64 65 66 69 70 71 73 74 75 76 78 79 80 81 82 83 84 86 87 88 89 90 91 92 93 94 95 96 97 98 99 100 101 102 103 104 105 106 107 108 109 110 111 112 113 114 115 116 117 118 119 128 129 138 139 159 160 161 166 174 175 176 177 180 181 182 183 184
P1V05_DSW_INT_CAP: R179.1 ; also on sheet 87
P1V05_DSW_INT_CAP_R: C252.1 R179.2
P1V05_ME_PWR_OPTION: C222.1 C223.1 C224.1 ; also on sheet 87
P1V05_PCH: C225.1 C226.1 C230.1 C232.1 C233.1 C234.1 C241.1 C242.1 C243.1 C244.1 C245.1 C278.1 C279.1 ; also on sheet 10 45 87 175
P1V5_PCH: C227.1 ; also on sheet 8 45 87 91 166
P1V05_VCCRTCEXT: C240.1 ; also on sheet 166
P1V5_VCCSST_INT_CAP: C246.1 ; also on sheet 87
P3V3: C235.1 C248.1 C249.1 C250.1 C253.1 R190.1 ; also on sheet 1 3 8 45 46 48 49 52 54 58 65 74 76 78 83 84 87 90 91 94 95 96 100 101 102 161 166 174 177 180 181 182 183
P3V3_STBY: C41.1 C81.1 C96.1 C228.1 C231.1 C236.1 C237.1 C247.1 C251.1 C277.1 C315.1 C370.1 C993.1 R216.2 R219.1 R247.1 R248.1 R762.1 R1577.1 R1578.1 R1579.1 R1586.1 R1587.1 R1588.1 R1894.1 R2054.2 U102.7(SD#) U102.8(VCC) U103.5(VCC) U170.14(VCC) U171.5(VCC) U172.5(VCC) U173.5(VCC) U174.5(VCC) U175.14(VCC) ; also on sheet 2 3 5 6 8 9 10 11 12 15 16 17 20 21 22 25 26 27 30 31 33 34 35 37 38 39 45 47 49 50 51 52 54 55 59 60 61 62 63 64 65 66 69 70 71 72 73 74 76 79 83 84 87 88 89 90 91 92 93 94 95 96 97 98 99 159 161 166 174 176 177 179 180 182 183 184
P3V_BAT: C238.1 C239.1 ; also on sheet 84 87 174 184
PVCCIO: C254.1 C255.1 C256.1 ; also on sheet 11 16 26 35 39 46 47 68 87 97 100 101 102 103 120 129 130 139 160 177 179 182
BMC_PWRBTN_N: R247.2 U172.2(B) ; also on sheet 180
BTN_FUNC_EN_N: R187.1 R265.1 ; also on sheet 177
FM_BMC_PWRBTN_OUT_N: R1579.2 R1605.2 U172.4(Y) ; also on sheet 90
FM_LVC3_CP: R1896.1 R1907.1 U102.1(CP)
FM_LVC3_D: R1897.1 R1906.1 U102.2(D)
FP_BTN_RESET_N2: Q85.S R1635.2 U170.8(O)
FP_PWR_BTN_N: R1605.1 ; also on sheet 51
FP_PWRBTN: R1581.1 U175.2(O)
FP_PWRBTN_N: PWRON1.1(T1) PWRON1.2(T2) R1580.1
FP_PWRBTN_R: R1581.2 U175.3(I)
FP_PWRBTN_RC_N: C1002.1 R1577.2 R1580.2 U175.1(I)
FP_RSTBTN: R1592.1 U175.6(O)
FP_RSTBTN_N: R1589.1 R1596.2 RESET1.1(T1) RESET1.2(T2)
FP_RSTBTN_R: R1592.2 U175.9(I)
FP_RSTBTN_RC_N: C1003.1 R1586.2 R1589.2 U175.5(I)
IRQ_LVC3_WAKE_DLY_EN: R1894.2 R1895.1 U170.6(O)
IRQ_LVC3_WAKE_EN: Q85.G R1895.2
IRQ_LVC3_WAKE_N: R1914.1 U103.1(A) ; also on sheet 64 74 81 83 88 94 95
IRQ_LVC3_WOL_N: R1908.1 R1913.1 R1914.2 U170.5(I)
IRQ_LVC3_WOL_N1: R1912.2 U103.4(Y)
IRQ_LVC3_WOL_N2: R1908.2 R1912.1 U170.9(I)
PCH_VCCPFUSE_3P3_R: C229.1 ; also on sheet 87
PWRBTN_FP_N: R368.1 R1578.2 R1583.2 U171.2(A) U175.4(O)
PWRBTN_OUT_N: R219.2 R368.2 U171.4(Y) U172.1(A)
ROW_EN: R1896.2 R1906.2 ; also on sheet 90
RST_BMC_RSTBTN_OUT_N: Q85.D R1588.2 R1635.1 U174.4(Y) ; also on sheet 182
RST_DBG_RSTBTN_N: R1596.1 ; also on sheet 69
RST_PERST0_N: U102.6(RD#) ; also on sheet 51 93 94 95
RSTBTN_BMC_OUT: R1594.1 ; also on sheet 180
RSTBTN_FP_N: R369.1 R1584.2 R1587.2 U173.2(A) U175.8(O)
RSTBTN_OUT_N: R248.2 R369.2 U173.4(Y) U174.1(A)
SSB_ROW_LATCH: R190.2 R1897.2 R1907.2 ; also on sheet 48
SYS_PWRBTN_N: R1583.1 ; also on sheet 180
SYS_RSTBTN_N: R1584.1 ; also on sheet 180
U171_OE: R187.2 R2054.1 U171.1(OE)
U173_OE: R216.1 R265.2 U173.1(OE)
U174_2: R762.2 R1594.2 U174.2(B)
WOL_LVC3_ROW: U102.3(Q#) U103.2(B)

Not connected (* = marked no-connect by the designer): U102 5(Q)*; U170 2(O)* 4(O)* 10(O)* 12(O)*; U175 10(O)* 12(O)*

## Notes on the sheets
sheet 168
- POWER/RESET BUTTON
- FAB2 REV003 20150721
- FAB1 20150315
- FAB1 REV011 20150407
- FAB1 20150210
- FROM BMC
- RED BTN
- TO BMC
- FROM CPLD
- FAB1 20150315
- FAB1 20150210
- BROWN BTN
- FROM BMC
- FAB1 REV011 20150407
- TO BMC
- FAB2 REV003 20150721
- FAB1 20150312
sheet 169
- CPU1 - GROUND (1/2)
sheet 170
- CPU1 - GROUND (2/2)
sheet 171
- CPU2 - GROUND (2/2)
sheet 172
- CPU2 - GROUND (1/2)
sheet 173
- WELLSBURG - DECOUPLING (1/2)
- 1.05V CORE/ASW/SUS FOR CORE SECTION
- CAD NOTE:
  PLACE ALL CAPS
  BSC STYLE
  NEAR TO PIN
  VCCCORE_1P05
- FAB1 REV013 20150414
- 3.3V SUS AZA SECTION
- 3.3V FUSE SECTION
- 3.3V SPI SECTION
- CAD NOTE:
  PLACE CAP
  (E) STYLE
  NEAR TO PIN
  VCCASW_1P05
- CAD NOTE:
  PLACE CAP
  (E) STYLE
  NEAR TO PIN
  VCCPFUSE_3P3
- CAD NOTE:
  PLACE ALL CAPS
  BSC STYLE
  NEAR TO PIN
  VCCASW_1P05
- CAD NOTE:
  PLACE CAP
  (R) STYLE
  NEAR TO PIN
  VCCPAZSUS_3P3
- CAD NOTE:
  PLACE CAP
  (R) STYLE
  NEAR TO PIN
  VCCPSPI_3P3
- 1.05V PCIE/DMI/SATA SECTION
- 1.05V CORE USB2 SECTION
- 3.3 CORE/SUS USB2 SECTION
- 3.3V DSW/RTC FOR RTC SECTION
- VCCRTCEXT: RTC
  DECOUPLING CAP ONLY
  SHOULD NOT BE DRIVEN
- CAD NOTE:
  PLACE CAP
  (R) STYLE
  NEAR TO PIN
  VCCMPHY_1P05
- CAD NOTE:
  PLACE CAP
  BSC STYLE
  NEAR TO PIN
  VCCAUSB_1P05
- CAD NOTE:
  PLACE CAP
  BSC STYLE
  NEAR TO PIN
  VCCDUSB_1P05
- CAD NOTE:
  PLACE CAP
  BSC STYLE
  NEAR TO PIN
  VCCAUSB_3P3
- CAD NOTE:
  PLACE CAP
  BSC STYLE
  NEAR TO PIN
  VCCUSBSUS_3P3
- CAD NOTE:
  PLACE CAP
  (R) STYLE
  NEAR TO PIN
  VCCPRTCSUS_3P3
- CAD NOTE:
  PLACE CAP
  (E) STYLE
  NEAR TO PIN
  VCCPRTC_3P3
- CAD NOTE:
  PLACE CAP
  (R) STYLE
  NEAR TO PIN
  VCCPRTC_3P3
- CAD NOTE:
  PLACE CAP
  (R) STYLE
  NEAR TO PIN
  VCCRTCEXT
- CAD NOTE:BSC STYLE PLACE 4 CAPS NEAR TO PIN VCCMPHY_1P05
- 3.3V CORE THERMAL SENSOR
- 3.3V SUS/DSW/CORE FOR GPIO/LPC SECTION
- GPIO/LPC SECTION
- CAD NOTE:
  PLACE CAP
  (E) STYLE
  NEAR TO PIN
  VCCPTS_3P3
- GPIO/LPC SECTION
- CAD NOTE:
  PLACE R AND C
  (R) STYLE
  NEAR TO PIN
  VCCDSW_1P05
- CAD NOTE:
  PLACE CAP
  (E) STYLE
  NEAR TO PIN
  VCCSST_1P5
- CAD NOTE:
  PLACE CAP
  BSC STYLE
  NEAR TO PIN
  VCCPSUS_3P3
- CAD NOTE:
  PLACE CAP
  BSC STYLE
  NEAR TO PIN
  VCCPCORE_3P3
- CAD NOTE:
  PLACE CAP
  (E) STYLE
  NEAR TO PIN
  VCCPDSW_3P3
- CAD NOTE:
  PLACE CAP
  BSC STYLE
  NEAR TO PIN
  VCCPCORE1_3P3
- DEEP SX WELL POWER (1.0 V / 1.1 V):
  THIS RAIL IS NORMALLY SUPPLIED BY AN INTERNAL
  VR FROM VCCPDSW    THIS PROVIDES A BYPASS OPTION
   IF THE INTERNAL VR IS DISABLED
  (AS A TEST MODE ONLY).
- INTERNALLY GENERATED
- VCCIO2PCH FOR CPU SECTION
- ROOM=WBG_DECOUPLING
- CAD NOTE:
  BSD: BACK SIDE COMPONENT
  E: EDGE
  R: RUN
